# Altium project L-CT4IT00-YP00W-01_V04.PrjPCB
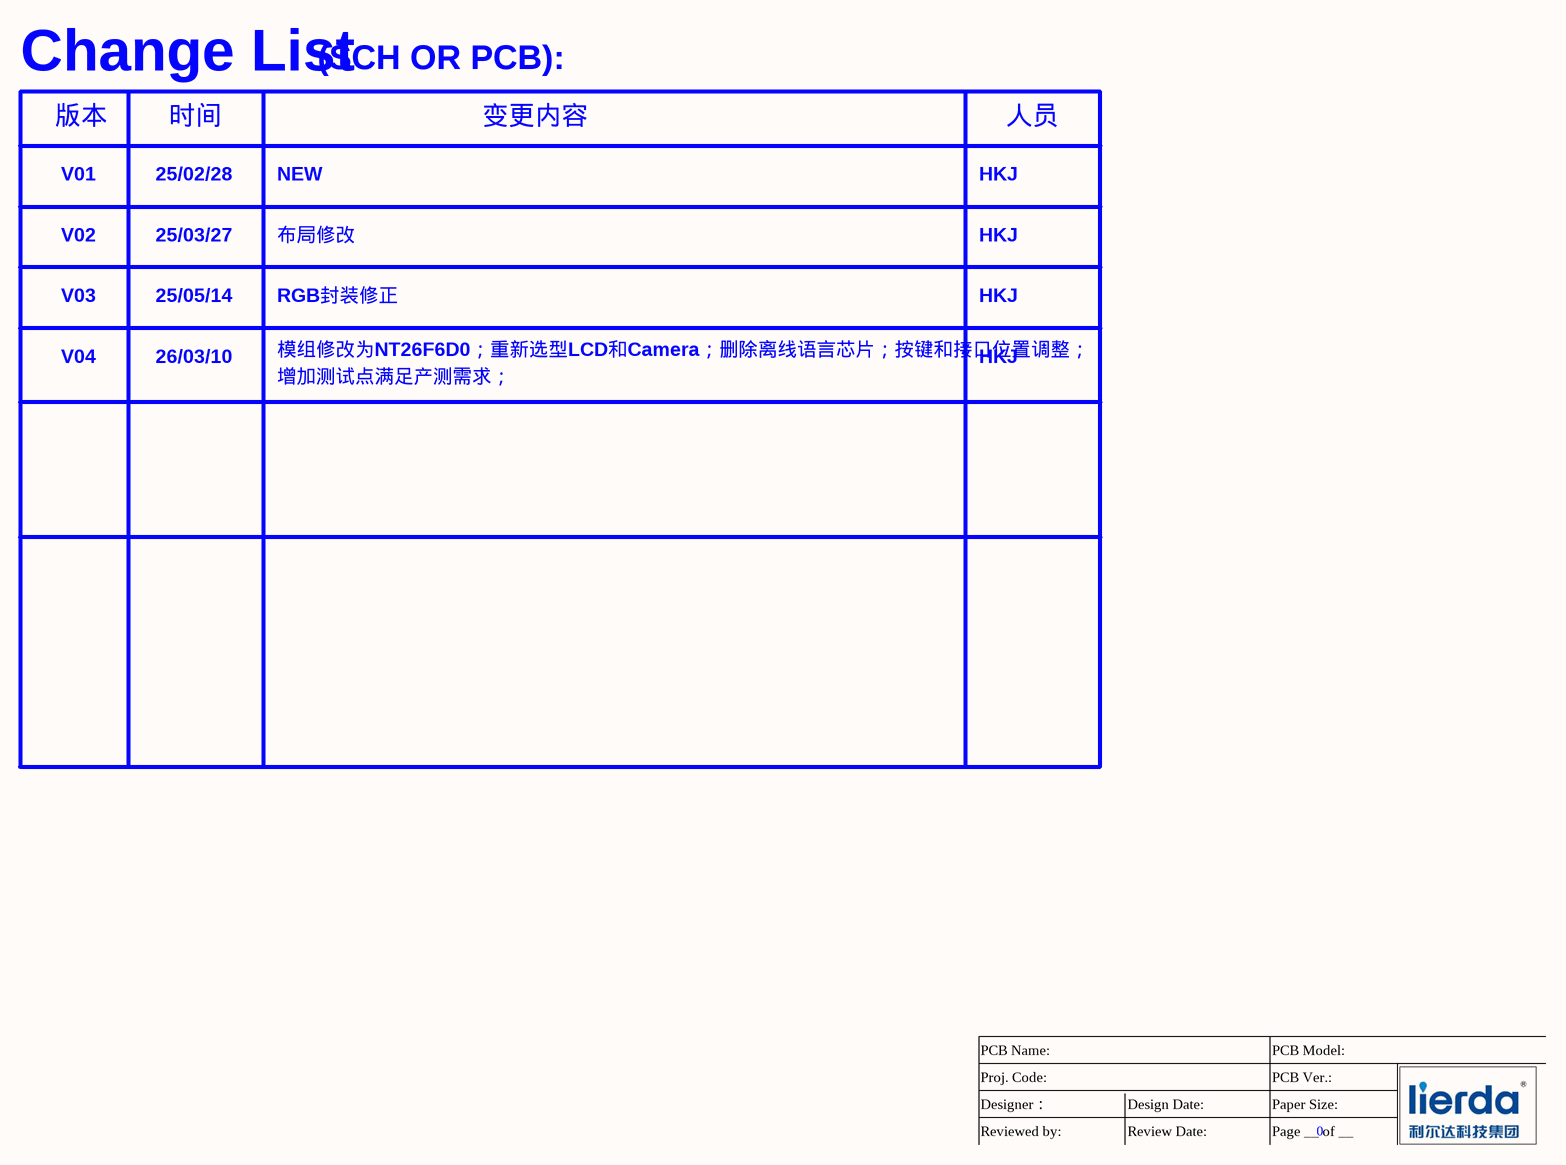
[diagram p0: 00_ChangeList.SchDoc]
项目型号: L-CT4IT00-YP00W-01; 项目名称: NT26FxDx OpenKit PCB; 立项编号: xxxx; 版本号: V04; 审核日期: 260318; 审核人员: SXT; 原理图页数: 4; 制图日期: 260317; 制图人员: HKJ
6 sheets, 214 parts. Net scope: global (net labels, ports and power ports of the same name join across sheets).
Board files: L-CT4IT00-YP00W-01_V04.PcbDoc, L-CT4IT00-YP00W-01-0402-04.PcbDoc
Sheets:
  00_ChangeList.SchDoc
  00_Block.SchDoc
  01_NT26FxDx.SchDoc
  02_Interfaces.SchDoc
  03_LED_KEY.SchDoc
  04_CODEC_PA.SchDoc

## Sheet 00_ChangeList.SchDoc
size A3

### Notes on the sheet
- Change List
- (SCH OR PCB):
- 版本
- V01
- 25/02/28
- 时间
- NEW
- 变更内容
- HKJ
- 人员
- V02
- 25/03/27
- 布局修改
- V03
- 25/05/14
- RGB封装修正
- V04
- 26/03/10
- 模组修改为NT26F6D0；重新选型LCD和Camera；删除离线语言芯片；按键和接口位置调整；
- 增加测试点满足产测需求；
- PCB Name:
- PCB Model:
- Designer：
- Proj. Code:
- Design Date:
- PCB Ver.:
- Paper Size:
- 0
- Reviewed by:
- Review Date:
- Page __ of __

## Sheet 00_Block.SchDoc
size A3
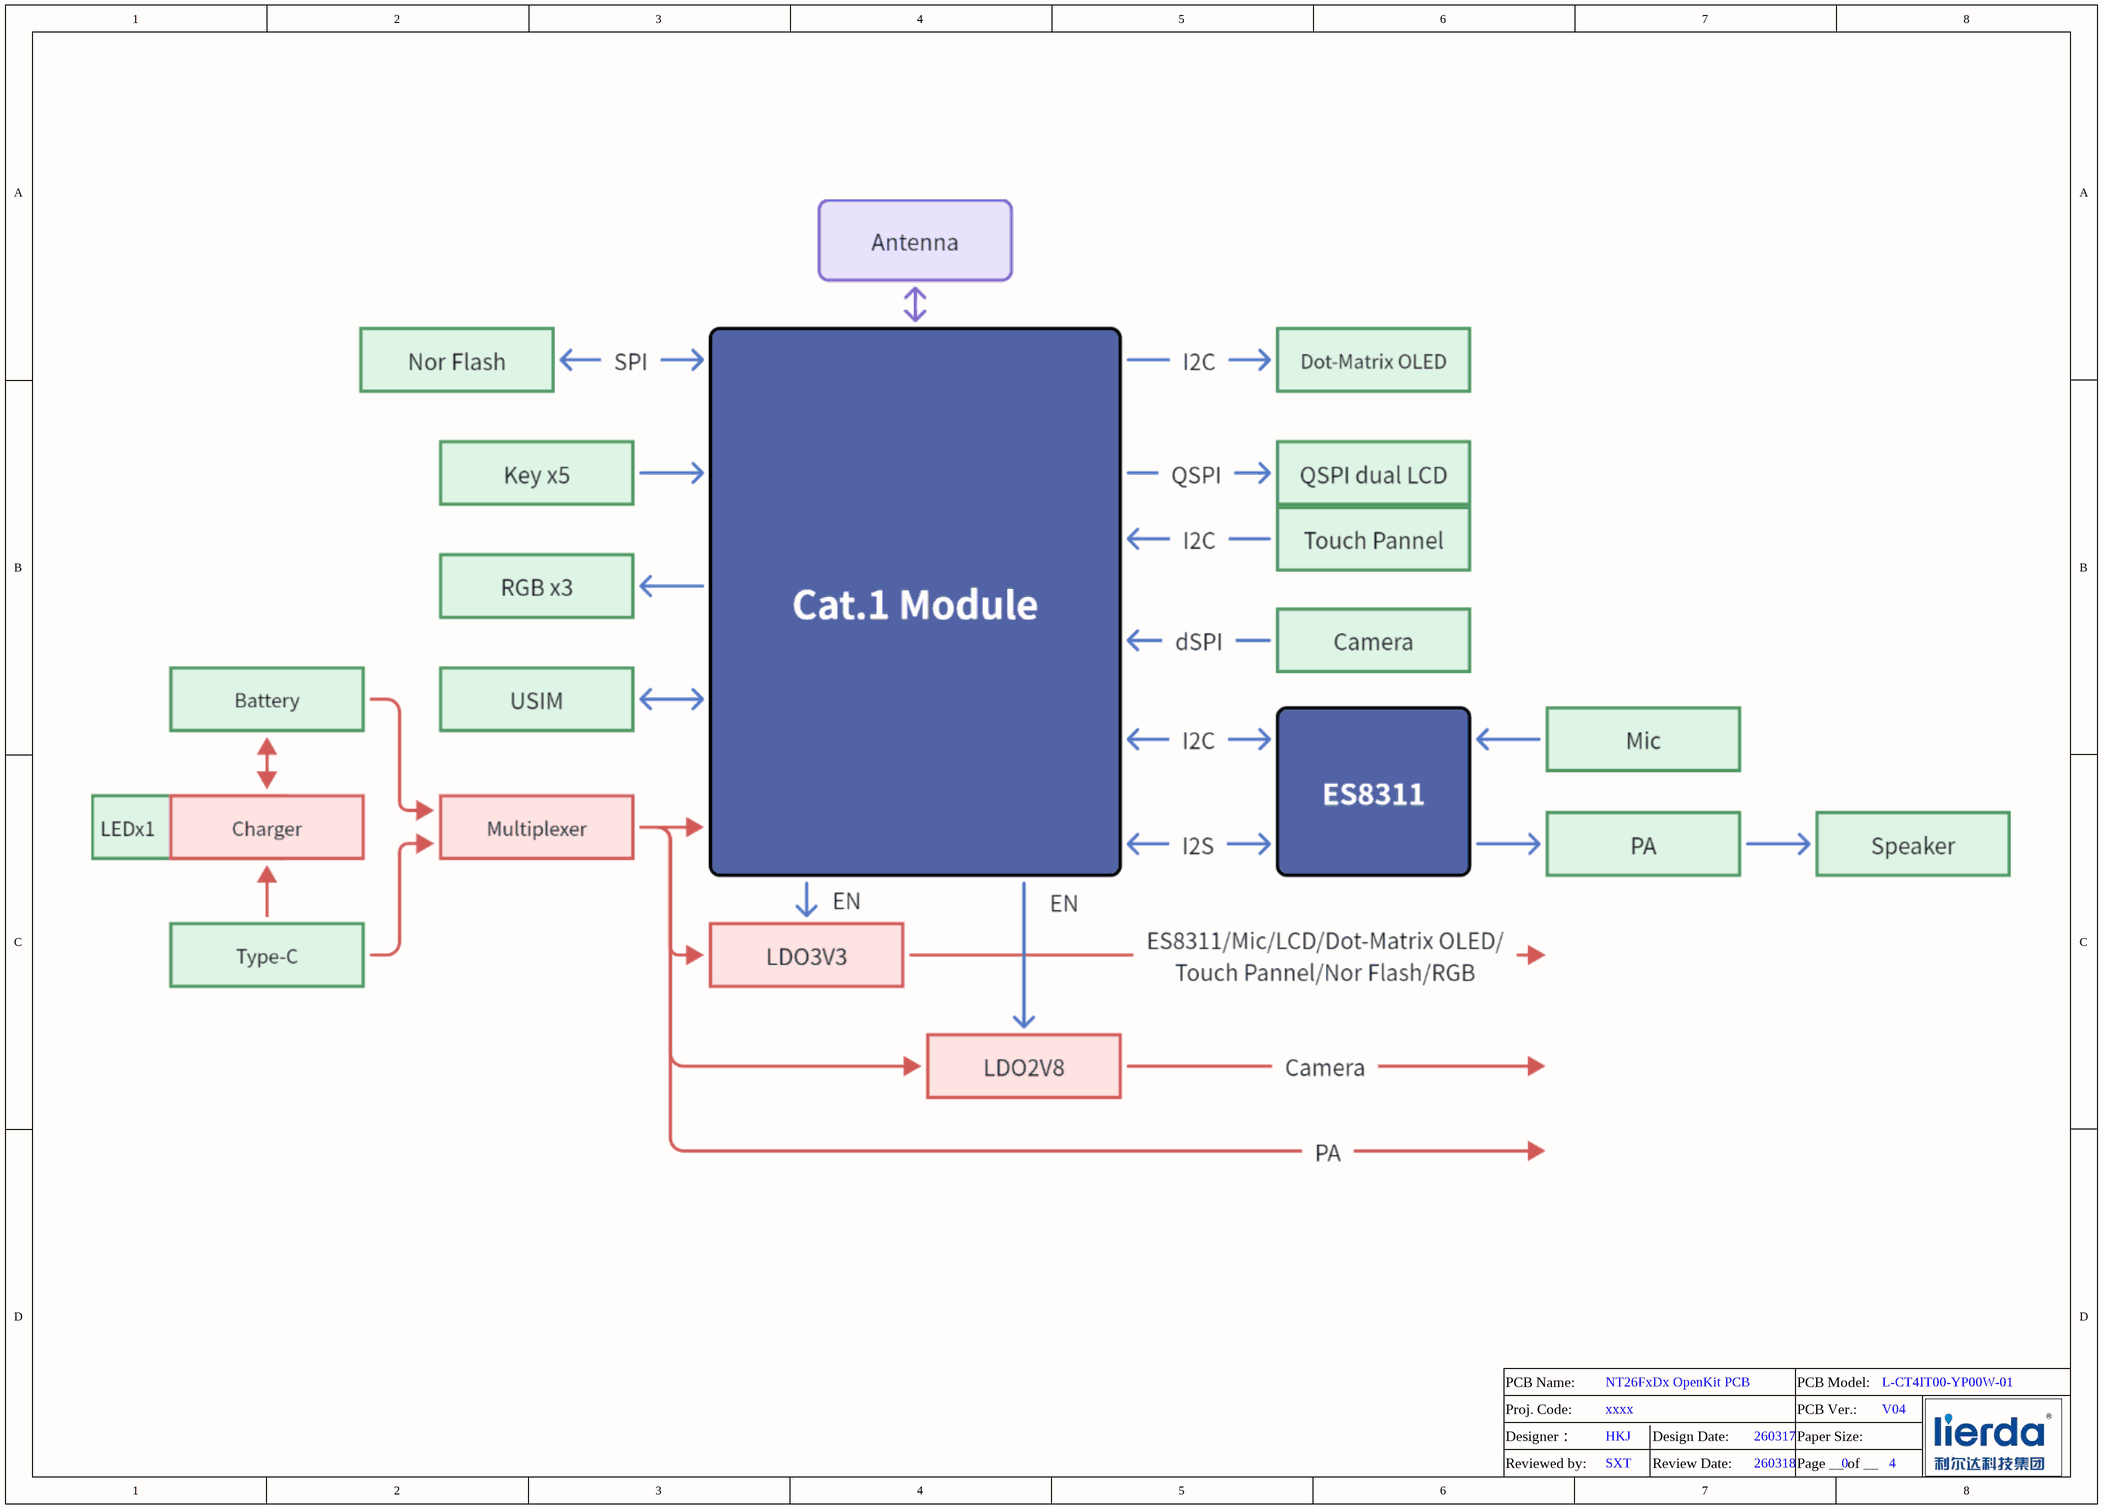
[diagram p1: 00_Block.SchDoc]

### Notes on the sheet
- PCB Name:
- PCB Model:
- Designer：
- Proj. Code:
- Design Date:
- PCB Ver.:
- Paper Size:
- 0
- Reviewed by:
- Review Date:
- Page __ of __

## Sheet 01_NT26FxDx.SchDoc
size A2
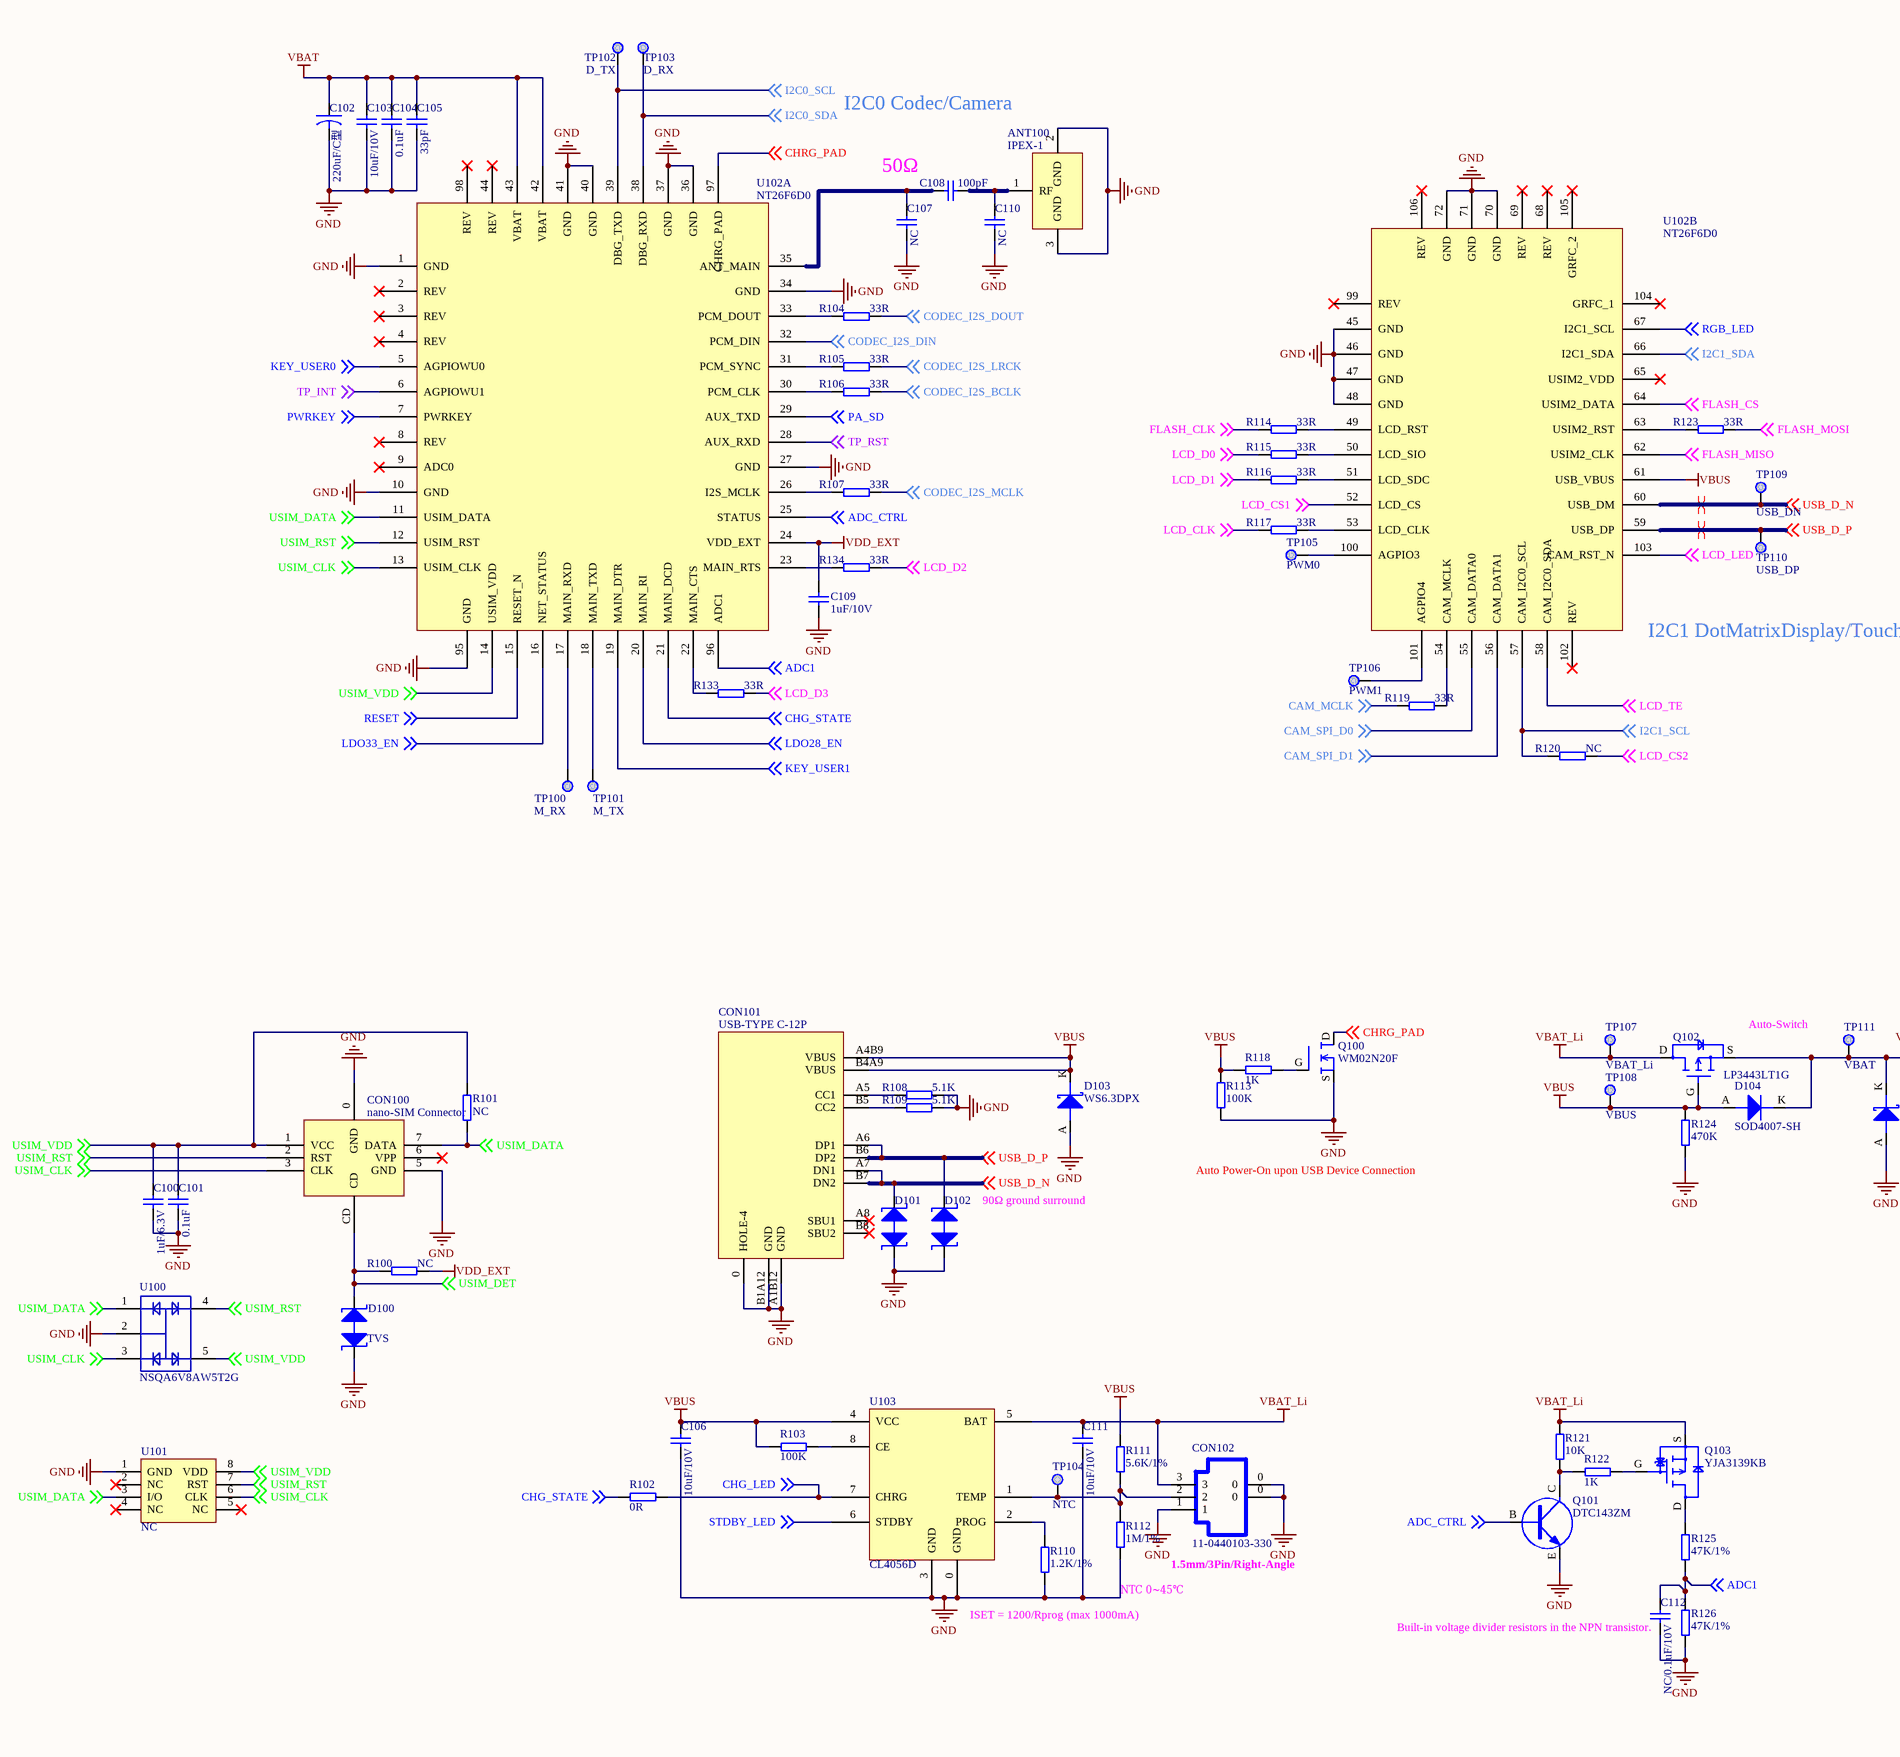
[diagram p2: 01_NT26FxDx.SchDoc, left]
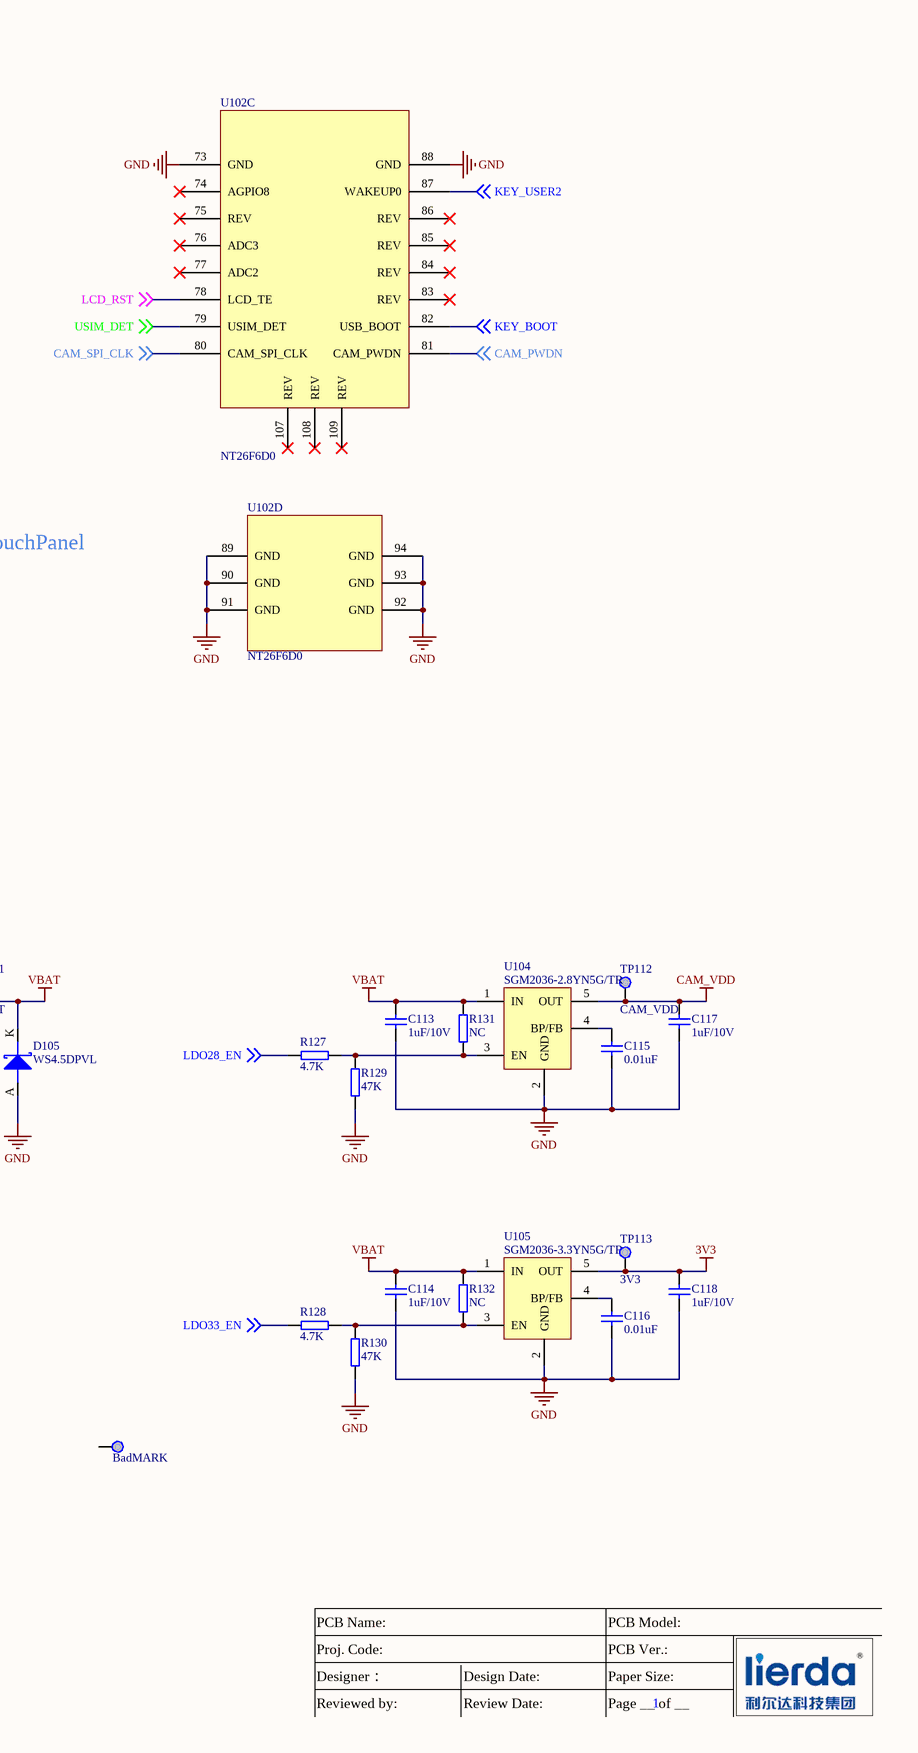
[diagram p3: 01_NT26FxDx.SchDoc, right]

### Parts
ANT100  IPEX-1  [IPX_U.FL-R-SMT-1]
BadMARK  BadMARK  [Bad Mark]  (value not drawn)
C100  1uF/6.3V  [0201_0.25D]
C101  0.1uF  [0201_0.25D]
C102  220uF/C型  [6032-TC]
C103  10uF/10V  [0402C_0.4D]
C104  0.1uF  [0201_0.25D]
C105  33pF  [0201_0.25D]
C106  10uF/10V  [0402C_0.4D]
C107  NC  [0201_0.25D]
C108  100pF  [0201_0.25D]
C109  1uF/10V  [0201_0.25D]
C110  NC  [0201_0.25D]
C111  10uF/10V  [0402C_0.4D]
C112  NC/0.1uF/10V  [0201_0.25D]
C113  1uF/10V  [0201_0.25D]
C114  1uF/10V  [0201_0.25D]
C115  0.01uF  [0201_0.25D]
C116  0.01uF  [0201_0.25D]
C117  1uF/10V  [0201_0.25D]
C118  1uF/10V  [0201_0.25D]
CON100  nano-SIM Connector  [SIM-MUP-C7801]
CON101  USB-TYPE C-12P  [TYPEC _6PIN板]
CON102  11-0440103-330  [SMD-1.5-3P]
D100  TVS  [DFN1006-NP]
D101  DIODE-2TVS-2  [DFN1006-NP]  (value not drawn)
D102  DIODE-2TVS-2  [DFN1006-NP]  (value not drawn)
D103  产品型号: WS6.3DPX  [UDFN2(1610)]  (hidden comment: DIODE-TVS)
D104  产品型号: SOD4007-SH  [SOD-123-FL]  (hidden comment: DIODE)
D105  产品型号: WS4.5DPVL  [UDFN2(1610)]  (hidden comment: DIODE-TVS)
Q100  WM02N20F  [DFN1006-3G]
Q101  DTC143ZM  [SOT-723-3A]
Q102  产品型号: LP3443LT1G  [SOT-23-3G]  (hidden comment: P-MOS-D1)
Q103  YJA3139KB  [DFN1006-3G]
R100  NC  [0201_0.25D]
R101  NC  [0201_0.25D]
R102  0R  [0201_0.25D]
R103  100K  [0201_0.25D]
R104  33R  [0201_0.25D]
R105  33R  [0201_0.25D]
R106  33R  [0201_0.25D]
R107  33R  [0201_0.25D]
R108  5.1K  [0201_0.25D]
R109  5.1K  [0201_0.25D]
R110  1.2K/1%  [0201_0.25D]
R111  5.6K/1%  [0201_0.25D]
R112  1M/1%  [0201_0.25D]
R113  100K  [0201_0.25D]
R114  33R  [0201_0.25D]
R115  33R  [0201_0.25D]
R116  33R  [0201_0.25D]
R117  33R  [0201_0.25D]
R118  1K  [0201_0.25D]
R119  33R  [0201_0.25D]
R120  NC  [0201_0.25D]
R121  10K  [0201_0.25D]
R122  1K  [0201_0.25D]
R123  33R  [0201_0.25D]
R124  470K  [0402R_0.4D]
R125  47K/1%  [0201_0.25D]
R126  47K/1%  [0201_0.25D]
R127  4.7K  [0201_0.25D]
R128  4.7K  [0201_0.25D]
R129  47K  [0201_0.25D]
R130  47K  [0201_0.25D]
R131  NC  [0201_0.25D]
R132  NC  [0201_0.25D]
R133  33R  [0201_0.25D]
R134  33R  [0201_0.25D]
TP100  M_RX  [TEST]
TP101  M_TX  [TEST]
TP102  D_TX  [TEST]
TP103  D_RX  [TEST]
TP104  NTC  [test]
TP105  PWM0  [TEST]
TP106  PWM1  [TEST]
TP107  VBAT_Li  [test]
TP108  VBUS  [test]
TP109  USB_DN  [test]
TP110  USB_DP  [test]
TP111  VBAT  [test]
TP112  CAM_VDD  [test]
TP113  3V3  [test]
U100  NSQA6V8AW5T2G  [SOT-323-5]
U101  NC  [DFN8(1.27)-6X5]
U102  NT26F6D0  [NT26-FCN B]  (parts A,B,C,D of 4)
U103  CL4056D  [SOP-8(1.27)-GND]
U104  产品型号: SGM2036-2.8YN5G/TR  [SOT-23-5P]  (hidden comment: SGM2036-XYN5G/TR)
U105  产品型号: SGM2036-3.3YN5G/TR  [SOT-23-5P]  (hidden comment: SGM2036-XYN5G/TR)

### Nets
3V3: C118.2 TP113.1 U105.5(OUT)
CAM_VDD: C117.2 TP112.1 U104.5(OUT)
GND: ANT100.2(GND) ANT100.3(GND) C100.1 C101.1 C102.2 C103.1 C104.1 C105.1 C106.1 C107.1 C109.1 C110.1 C111.1 C112.1 C113.1 C114.1 C115.1 C116.1 C117.1 C118.1 CON100.0(GND) CON100.5(GND) CON101.0(HOLE-4) CON101.A1B12(GND) CON101.B1A12(GND) CON102.0 CON102.1 D100.A D101.A D102.A D103.A D105.A Q100.S Q101.E R108.2 R109.2 R110.2 R112.2 R113.1 R124.1 R126.1 R129.1 R130.1 U100.2 U101.1(GND) U102.1(GND) U102.10(GND) U102.27(GND) U102.34(GND) U102.36(GND) U102.37(GND) U102.40(GND) U102.41(GND) U102.45(GND) U102.46(GND) U102.47(GND) U102.48(GND) U102.70(GND) U102.71(GND) U102.72(GND) U102.73(GND) U102.88(GND) U102.89(GND) U102.90(GND) U102.91(GND) U102.92(GND) U102.93(GND) U102.94(GND) U102.95(GND) U103.0(GND) U103.3(GND) U104.2(GND) U105.2(GND)
VBAT: C102.1 C103.2 C104.2 C105.2 C113.2 C114.2 D104.K D105.K Q102.S R131.1 R132.1 TP111.1 U102.42(VBAT) U102.43(VBAT) U104.1(IN) U105.1(IN)
VBAT_Li: C111.2 CON102.3 Q102.D Q103.S R121.2 TP107.1 U103.5(BAT)
VBUS: C106.2 CON101.A4B9(VBUS) CON101.B4A9(VBUS) D103.K D104.A Q102.G R103.2 R111.1 R113.2 R118.2 R124.2 TP108.1 U102.61(USB_VBUS) U103.4(VCC)
VDD_EXT: C109.2 R100.1 U102.24(VDD_EXT)
ADC1: C112.2 R125.1 R126.2 U102.96(ADC1) ; off-sheet ADC1
ADC_CTRL: Q101.B U102.25(STATUS) ; off-sheet ADC_CTRL
CAM_MCLK: R119.1 ; off-sheet CAM_MCLK
CAM_PWDN: U102.81(CAM_PWDN) ; off-sheet CAM_PWDN
CAM_SPI_CLK: U102.80(CAM_SPI_CLK) ; off-sheet CAM_SPI_CLK
CAM_SPI_D0: U102.55(CAM_DATA0) ; off-sheet CAM_SPI_D0
CAM_SPI_D1: U102.56(CAM_DATA1) ; off-sheet CAM_SPI_D1
CHG_LED: R102.2 U103.7(CHRG) ; off-sheet CHG_LED
CHG_STATE: R102.1 U102.21(MAIN_DCD) ; off-sheet CHG_STATE
CHRG_PAD: Q100.D U102.97(CHRG_PAD) ; off-sheet CHRG_PAD
CODEC_I2S_BCLK: R106.2 ; off-sheet CODEC_I2S_BCLK
CODEC_I2S_DIN: U102.32(PCM_DIN) ; off-sheet CODEC_I2S_DIN
CODEC_I2S_DOUT: R104.2 ; off-sheet CODEC_I2S_DOUT
CODEC_I2S_LRCK: R105.2 ; off-sheet CODEC_I2S_LRCK
CODEC_I2S_MCLK: R107.2 ; off-sheet CODEC_I2S_MCLK
FLASH_CLK: R114.2 ; off-sheet FLASH_CLK
FLASH_CS: U102.64(USIM2_DATA) ; off-sheet FLASH_CS
FLASH_MISO: U102.62(USIM2_CLK) ; off-sheet FLASH_MISO
FLASH_MOSI: R123.2 ; off-sheet FLASH_MOSI
I2C0_SCL: TP102.1 U102.39(DBG_TXD) ; off-sheet I2C0_SCL
I2C0_SDA: TP103.1 U102.38(DBG_RXD) ; off-sheet I2C0_SDA
I2C1_SCL: R120.1 U102.57(CAM_I2C0_SCL) ; off-sheet I2C1_SCL
I2C1_SDA: U102.66(I2C1_SDA) ; off-sheet I2C1_SDA
KEY_BOOT: U102.82(USB_BOOT) ; off-sheet KEY_BOOT
KEY_USER0: U102.5(AGPIOWU0) ; off-sheet KEY_USER0
KEY_USER1: U102.19(MAIN_DTR) ; off-sheet KEY_USER1
KEY_USER2: U102.87(WAKEUP0) ; off-sheet KEY_USER2
LCD_CLK: R117.1 ; off-sheet LCD_CLK
LCD_CS1: U102.52(LCD_CS) ; off-sheet LCD_CS1
LCD_CS2: R120.2 ; off-sheet LCD_CS2
LCD_D0: R115.1 ; off-sheet LCD_D0
LCD_D1: R116.1 ; off-sheet LCD_D1
LCD_D2: R134.2 ; off-sheet LCD_D2
LCD_D3: R133.2 ; off-sheet LCD_D3
LCD_LED: U102.103(CAM_RST_N) ; off-sheet LCD_LED
LCD_RST: U102.78(LCD_TE) ; off-sheet LCD_RST
LCD_TE: U102.58(CAM_I2C0_SDA) ; off-sheet LCD_TE
LDO28_EN: R127.1 U102.20(MAIN_RI) ; off-sheet LDO28_EN
LDO33_EN: R128.1 U102.16(NET_STATUS) ; off-sheet LDO33_EN
PA_SD: U102.29(AUX_TXD) ; off-sheet PA_SD
PWRKEY: U102.7(PWRKEY) ; off-sheet PWRKEY
RESET: U102.15(RESET_N) ; off-sheet RESET
RGB_LED: U102.67(I2C1_SCL) ; off-sheet RGB_LED
STDBY_LED: U103.6(STDBY) ; off-sheet STDBY_LED
TP_INT: U102.6(AGPIOWU1) ; off-sheet TP_INT
TP_RST: U102.28(AUX_RXD) ; off-sheet TP_RST
USB_D_N: CON101.A7(DN1) CON101.B7(DN2) D101.K TP109.1 U102.60(USB_DM) ; off-sheet USB_D_N
USB_D_P: CON101.A6(DP1) CON101.B6(DP2) D102.K TP110.1 U102.59(USB_DP) ; off-sheet USB_D_P
USIM_CLK: CON100.3(CLK) U100.3 U101.6(CLK) U102.13(USIM_CLK) ; off-sheet USIM_CLK
USIM_DATA: CON100.7(DATA) R101.1 U100.1 U101.3(I/O) U102.11(USIM_DATA) ; off-sheet USIM_DATA
USIM_DET: CON100.CD D100.K R100.2 U102.79(USIM_DET) ; off-sheet USIM_DET
USIM_RST: CON100.2(RST) U100.4 U101.7(RST) U102.12(USIM_RST) ; off-sheet USIM_RST
USIM_VDD: C100.2 C101.2 CON100.1(VCC) R101.2 U100.5 U101.8(VDD) U102.14(USIM_VDD) ; off-sheet USIM_VDD
NetANT100_1: ANT100.1(RF) C108.1 C110.2
NetC107_2: C107.2 C108.2 U102.35(ANT_MAIN)
NetC115_2: C115.2 U104.4(BP/FB)
NetC116_2: C116.2 U105.4(BP/FB)
NetCON101_A5: CON101.A5(CC1) R108.1
NetCON101_B5: CON101.B5(CC2) R109.1
NetCON102_2: CON102.2 R111.2 R112.1 TP104.1 U103.1(TEMP)
NetQ100_G: Q100.G R118.1
NetQ101_C: Q101.C R121.1 R122.2
NetQ103_D: Q103.D R125.2
NetQ103_G: Q103.G R122.1
NetR103_1: R103.1 U103.8(CE)
NetR104_1: R104.1 U102.33(PCM_DOUT)
NetR105_1: R105.1 U102.31(PCM_SYNC)
NetR106_1: R106.1 U102.30(PCM_CLK)
NetR107_1: R107.1 U102.26(I2S_MCLK)
NetR110_1: R110.1 U103.2(PROG)
NetR114_1: R114.1 U102.49(LCD_RST)
NetR115_2: R115.2 U102.50(LCD_SIO)
NetR116_2: R116.2 U102.51(LCD_SDC)
NetR117_2: R117.2 U102.53(LCD_CLK)
NetR119_2: R119.2 U102.54(CAM_MCLK)
NetR123_1: R123.1 U102.63(USIM2_RST)
NetR127_2: R127.2 R129.2 R131.2 U104.3(EN)
NetR128_2: R128.2 R130.2 R132.2 U105.3(EN)
NetR133_1: R133.1 U102.22(MAIN_CTS)
NetR134_1: R134.1 U102.23(MAIN_RTS)
NetTP100_1: TP100.1 U102.17(MAIN_RXD)
NetTP101_1: TP101.1 U102.18(MAIN_TXD)
NetTP105_1: TP105.1 U102.100(AGPIO3)
NetTP106_1: TP106.1 U102.101(AGPIO4)

Not connected (* = marked no-connect by the designer): BadMARK 1; CON100 6(VPP)*; CON101 A8(SBU1)* B8(SBU2)*; U101 2(NC)* 4(NC)* 5(NC)*; U102 2(REV)* 3(REV)* 4(REV)* 8(REV)* 9(ADC0)* 44(REV)* 65(USIM2_VDD)* 68(REV)* 69(REV)* 74(AGPIO8)* 75(REV)* 76(ADC3)* 77(ADC2)* 83(REV)* 84(REV)* 85(REV)* 86(REV)* 98(REV)* 99(REV)* 102(REV)* 104(GRFC_1)* 105(GRFC_2)* 106(REV)* 107(REV)* 108(REV)* 109(REV)*

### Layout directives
differential pair: USB_D_N, USB_D_P

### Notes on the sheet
- (near ANT100) I2C0 Codec/Camera
- 50Ω
- (near U102) I2C1 DotMatrixDisplay/TouchPanel
- Auto-Switch
- (near D102) 90Ω ground surround
- Auto Power‑On upon USB Device Connection
- (near R112) NTC 0~45℃
- 1.5mm/3Pin/Right-Angle
- ISET = 1200/Rprog (max 1000mA)
- Built-in voltage divider resistors in the NPN transistor.
- PCB Name:
- PCB Model:
- Designer：
- Reviewed by:
- Proj. Code:
- Design Date:
- Review Date:
- PCB Ver.:
- Paper Size:
- Page __ of __
- 1

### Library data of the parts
ANT100 = 1416000325: DC-6GHz; 产品型号: SL2-240006-A; 品名: RF测试座; 原厂品牌: 森岭; 封装: SMD; 物料状态: 优选
C100 C109 C112-C114 C117 C118 = 1405002136: 1uF/6.3V/20%/X5R; 产品型号: CL03A105MQ3CSNH; 品名: 陶瓷电容; 原厂品牌: SAMSUNG电容; 封装: 0201; 物料状态: 优选
C101 C104 = 1405001272: 0.1uF/10V/10%/X5R; 品名: 陶瓷电容; 原厂品牌: 微容VIIYONG; 封装: 0201; 物料状态: 优选
C102 = 1405000173: 220uF/6.3V/10%/1.2Ω; 产品型号: TAJC227K006RNJ; 品名: 钽电容; 原厂品牌: AVX; 封装: C型; 物料状态: 优选
C103 C106 C111 = 1405001308: 10uF/10V/20%/X5R; 产品型号: CL05A106MP5NUNC; 品名: 陶瓷电容; 原厂品牌: SAMSUNG电容; 封装: 0402; 物料状态: 优选
C105 C107 C108 C110 = 1405002411: 33pF/50V/5%/C0G; 产品型号: V330J0201C0G500NAT; 品名: 陶瓷电容; 原厂品牌: 微容VIIYONG; 封装: 0201; 物料状态: 优选
C115 C116 = 1405001481: 10nF/16V/10%/X7R; 产品型号: CC0201KRX7R7BB103; 品名: 陶瓷电容; 原厂品牌: YAGEO; 封装: 0201; 物料状态: 优选
CON100 = 1416003211: Push-Push NANO-SIM Card Connector; 产品型号: MUP-C7801-2; 品名: 卡座连接器; 原厂品牌: 德海威; 封装: SMD; 物料状态: 优选
CON101 = 1416003448: USB Type-C; 产品型号: U20405-2; 封装: SMD; 品名: USB连接器; 物料状态: 优选; 原厂品牌: 德海威
CON102 = 1416001211: 1.25mm/3PIN; 产品型号: CNT-W125-1*3-TDM-185; 存货编码: 1416002837; 品名: 线对板连接器; 原厂品牌: 肯耐特; 封装: SMD; 物料状态: 优选
D100 = 1409004149: 1通道; 产品型号: WS05DPF-BH; 品名: ESD保护器件; 原厂品牌: WAYON（维安）; 封装: DFN1006-2L; 物料状态: 优选
D101 D102 = 1409004148: 1通道; 产品型号: WS6183KF; 品名: ESD保护器件; 原厂品牌: WAYON（维安）; 封装: DFN1006-2L; 物料状态: 优选
D103 = 1409004319: 1通道; 品名: ESD保护器件; 原厂品牌: WAYON（维安）; 封装: DFN1610-2L; 物料状态: 优选
D104 = 1409001001: 1000V/1A; 品名: 整流二极管; 原厂品牌: LRC; 封装: SOD-123FL; 物料状态: 优选
D105 = 1409003028: 1通道/4.5V/12V/2160W/600pF; 品名: ESD保护器件; 原厂品牌: WAYON（维安）; 封装: DFN1610-2L; 物料状态: 优选
Q100 = N-MOS
Q101 = 1412002731: NPN/100mA/50V/100mW; 品名: 三极管; 原厂品牌: CJ; 封装: SOT-723; 物料状态: 优选
Q102 = 1412000290: PMOS/20V/4.7A; 品名: MOS管; 原厂品牌: LRC; 封装: SOT-23; 物料状态: 优选
Q103 = 1412003096: PMOS/-20V/0.65A; 品名: MOS管; 原厂品牌: YJ; 封装: DFN1006-3F; 物料状态: 优选
R100 R101 R103 R108 R109 R118 R121 R122 = 1408005605: 5.1KΩ/1%; 产品型号: 0201WMF5101TEE; 品名: 厚膜贴片电阻; 原厂品牌: Uniohm; 封装: 0201; 物料状态: 优选
R102 R110-R112 = 1408001444: 10KΩ/5%; 产品型号: RC0201JR-0710KL; 品名: 厚膜贴片电阻; 原厂品牌: YAGEO; 封装: 0201; 物料状态: 优选
R104-R107 R114-R117 R119 R120 R123 R133 R134 = 1408001443: 33Ω/5%; 产品型号: RC0201JR-0733RL; 品名: 厚膜贴片电阻; 原厂品牌: YAGEO; 封装: 0201; 物料状态: 优选
R113 = 1408005604: 10K/5%; 产品型号: 10K; 器件名称: 厚膜贴片电阻; 原厂品牌: Uniohm; 封装: 0201
R124 = 1408000869: 1M/5%; 产品型号: RC0402JR-071ML; 品名: 厚膜贴片电阻; 原厂品牌: YAGEO; 封装: 0402; 物料状态: 优选
R125 R126 R129 R130 = 1408001835: 47KΩ/1%; 产品型号: RC0201FR-0747KL; 品名: 厚膜贴片电阻; 原厂品牌: YAGEO; 封装: 0201; 物料状态: 优选
R127 R128 = 1408001558: 4.7KΩ/5%; 产品型号: RC0201JR-074K7L; 品名: 厚膜贴片电阻; 原厂品牌: YAGEO; 封装: 0201; 物料状态: 优选
R131 R132 = 1408005685: 100KΩ/5%; 产品型号: 0201WMJ0104TEE; 品名: 厚膜贴片电阻; 原厂品牌: Uniohm; 封装: 0201; 物料状态: 优选
TP100-TP103 TP105 TP106 = TP
TP104 TP107-TP113 = MARK
U100 = 1409000217: 双向/7.14V/600W; 器件名称: TVS管; 原厂品牌: Onsemi
U101 = 180006-03G: 存货编码: 1410013522; 封装: MFF2; 型号: 28991070003-FA; 品牌: 不指定（客供料）
U103 = CL4056
U104 = 1407001782: 2.8V/300mA/1.6-5.5V; 品名: 低压差线性稳压器; 原厂品牌: 圣邦微; 封装: SOT-23-5; 物料状态: 优选
U105 = 1407000926: 3.3V/300mA/1.6-5.5V; 品名: 低压差线性稳压器; 原厂品牌: 圣邦微; 封装: SOT-23-5; 物料状态: 优选

## Sheet 02_Interfaces.SchDoc
size A3
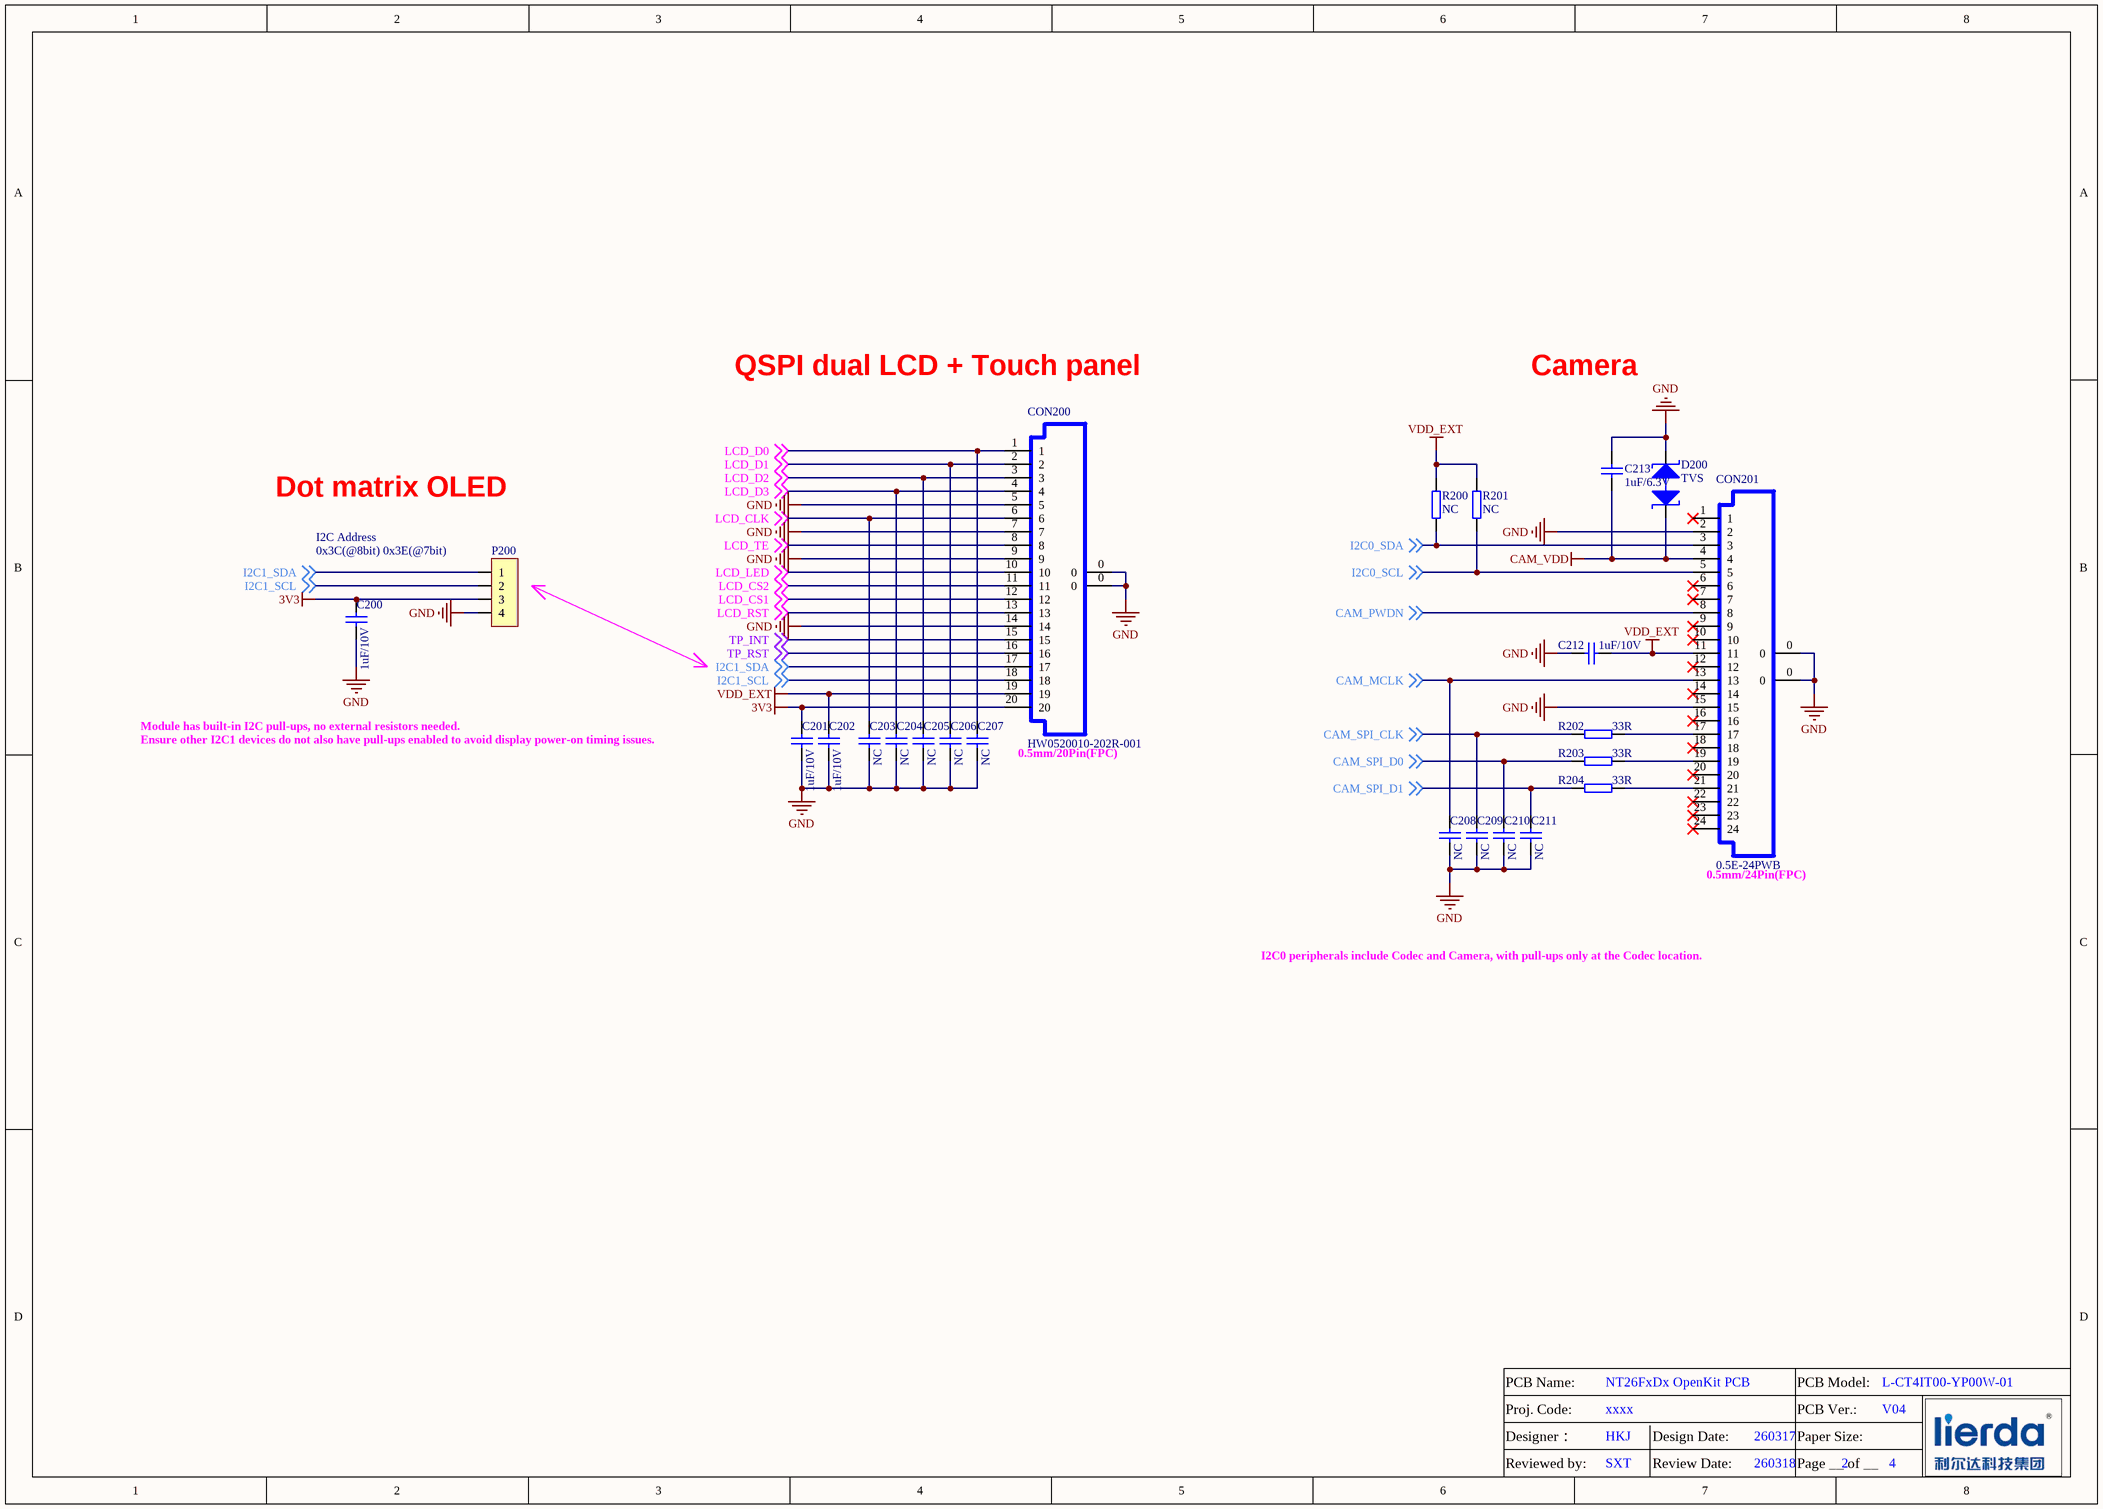
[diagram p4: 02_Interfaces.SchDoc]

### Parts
C200  1uF/10V  [0201_0.25D]
C201  1uF/10V  [0201_0.25D]
C202  1uF/10V  [0201_0.25D]
C203  NC  [0201_0.25D]
C204  NC  [0201_0.25D]
C205  NC  [0201_0.25D]
C206  NC  [0201_0.25D]
C207  NC  [0201_0.25D]
C208  NC  [0201_0.25D]
C209  NC  [0201_0.25D]
C210  NC  [0201_0.25D]
C211  NC  [0201_0.25D]
C212  1uF/10V  [0201_0.25D]
C213  1uF/6.3V  [0201_0.25D]
CON200  HW0520010-202R-001  [FPC0.5E-20P]
CON201  产品型号: 0.5E-24PWB  [0.5S-3S-24PWB]  (hidden comment: FPC-24)
D200  TVS  [DFN1006-NP]
P200  SPI 4-M  [SIP 2.54_4_S]  (value not drawn)
R200  NC  [0201_0.25D]
R201  NC  [0201_0.25D]
R202  33R  [0201_0.25D]
R203  33R  [0201_0.25D]
R204  33R  [0201_0.25D]

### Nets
3V3: C200.2 C201.1 CON200.20 P200.3
CAM_VDD: C213.1 CON201.4 D200.K
GND: C200.1 C201.2 C202.2 C203.1 C204.1 C205.1 C206.1 C207.1 C208.1 C209.1 C210.1 C211.1 C212.2 C213.2 CON200.0 CON200.5 CON200.7 CON200.9 CON200.14 CON201.0 CON201.2 CON201.15 D200.A P200.4
VDD_EXT: C202.1 C212.1 CON200.19 CON201.11 R200.2 R201.2
CAM_MCLK: C208.2 CON201.13 ; off-sheet CAM_MCLK
CAM_PWDN: CON201.8 ; off-sheet CAM_PWDN
CAM_SPI_CLK: C209.2 R202.1 ; off-sheet CAM_SPI_CLK
CAM_SPI_D0: C210.2 R203.1 ; off-sheet CAM_SPI_D0
CAM_SPI_D1: C211.2 R204.1 ; off-sheet CAM_SPI_D1
I2C0_SCL: CON201.5 R201.1 ; off-sheet I2C0_SCL
I2C0_SDA: CON201.3 R200.1 ; off-sheet I2C0_SDA
I2C1_SCL: CON200.18 P200.2 ; off-sheet I2C1_SCL
I2C1_SDA: CON200.17 P200.1 ; off-sheet I2C1_SDA
LCD_CLK: C203.2 CON200.6 ; off-sheet LCD_CLK
LCD_CS1: CON200.12 ; off-sheet LCD_CS1
LCD_CS2: CON200.11 ; off-sheet LCD_CS2
LCD_D0: C207.2 CON200.1 ; off-sheet LCD_D0
LCD_D1: C206.2 CON200.2 ; off-sheet LCD_D1
LCD_D2: C205.2 CON200.3 ; off-sheet LCD_D2
LCD_D3: C204.2 CON200.4 ; off-sheet LCD_D3
LCD_LED: CON200.10 ; off-sheet LCD_LED
LCD_RST: CON200.13 ; off-sheet LCD_RST
LCD_TE: CON200.8 ; off-sheet LCD_TE
TP_INT: CON200.15 ; off-sheet TP_INT
TP_RST: CON200.16 ; off-sheet TP_RST
NetCON201_17: CON201.17 R202.2
NetCON201_19: CON201.19 R203.2
NetCON201_21: CON201.21 R204.2

Not connected (* = marked no-connect by the designer): CON201 1* 6* 7* 9* 10* 12* 14* 16* 18* 20* 22* 23* 24*

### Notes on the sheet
- QSPI dual LCD + Touch panel
- Camera
- Dot matrix OLED
- I2C Address
- 0x3C(@8bit) 0x3E(@7bit)
- Module has built-in I2C pull-ups, no external resistors needed.
- Ensure other I2C1 devices do not also have pull-ups enabled to avoid display power-on timing issues.
- 0.5mm/20Pin(FPC)
- (near CON201) 0.5mm/24Pin(FPC)
- I2C0 peripherals include Codec and Camera, with pull-ups only at the Codec location.
- PCB Name:
- PCB Model:
- Designer：
- Proj. Code:
- Design Date:
- PCB Ver.:
- Paper Size:
- 2
- Reviewed by:
- Review Date:
- Page __ of __

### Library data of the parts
C200-C202 C212 C213 = 1405002136: as C100 on sheet 01_NT26FxDx
C203-C211 = 1405002411: as C105 on sheet 01_NT26FxDx
CON200 = 1416002856: 0.50mm/20PIN; 产品型号: 60030-2001-5002; 品名: FFC，FPC连接器; 原厂品牌: 新富尔; 封装: SMD; 物料状态: 优选
CON201 = 1416000423: 0.50mm/24PIN; 品名: FFC，FPC连接器; 原厂品牌: 乐清华宝; 封装: SMD; 物料状态: 优选
D200 = 1409004149: as D100 on sheet 01_NT26FxDx
P200 = 1416000794: 2.54mm/1*4PIN/直; 产品型号: PH2.54排针1X4P/L=11.6 PA=6 PC=3 H=2.5; 品名: 排针; 原厂品牌: 联益; 封装: DIP; 物料状态: 优选
R200 R201 = 1408005605: as R100 on sheet 01_NT26FxDx
R202-R204 = 1408001443: as R104 on sheet 01_NT26FxDx

## Sheet 03_LED_KEY.SchDoc
size A3
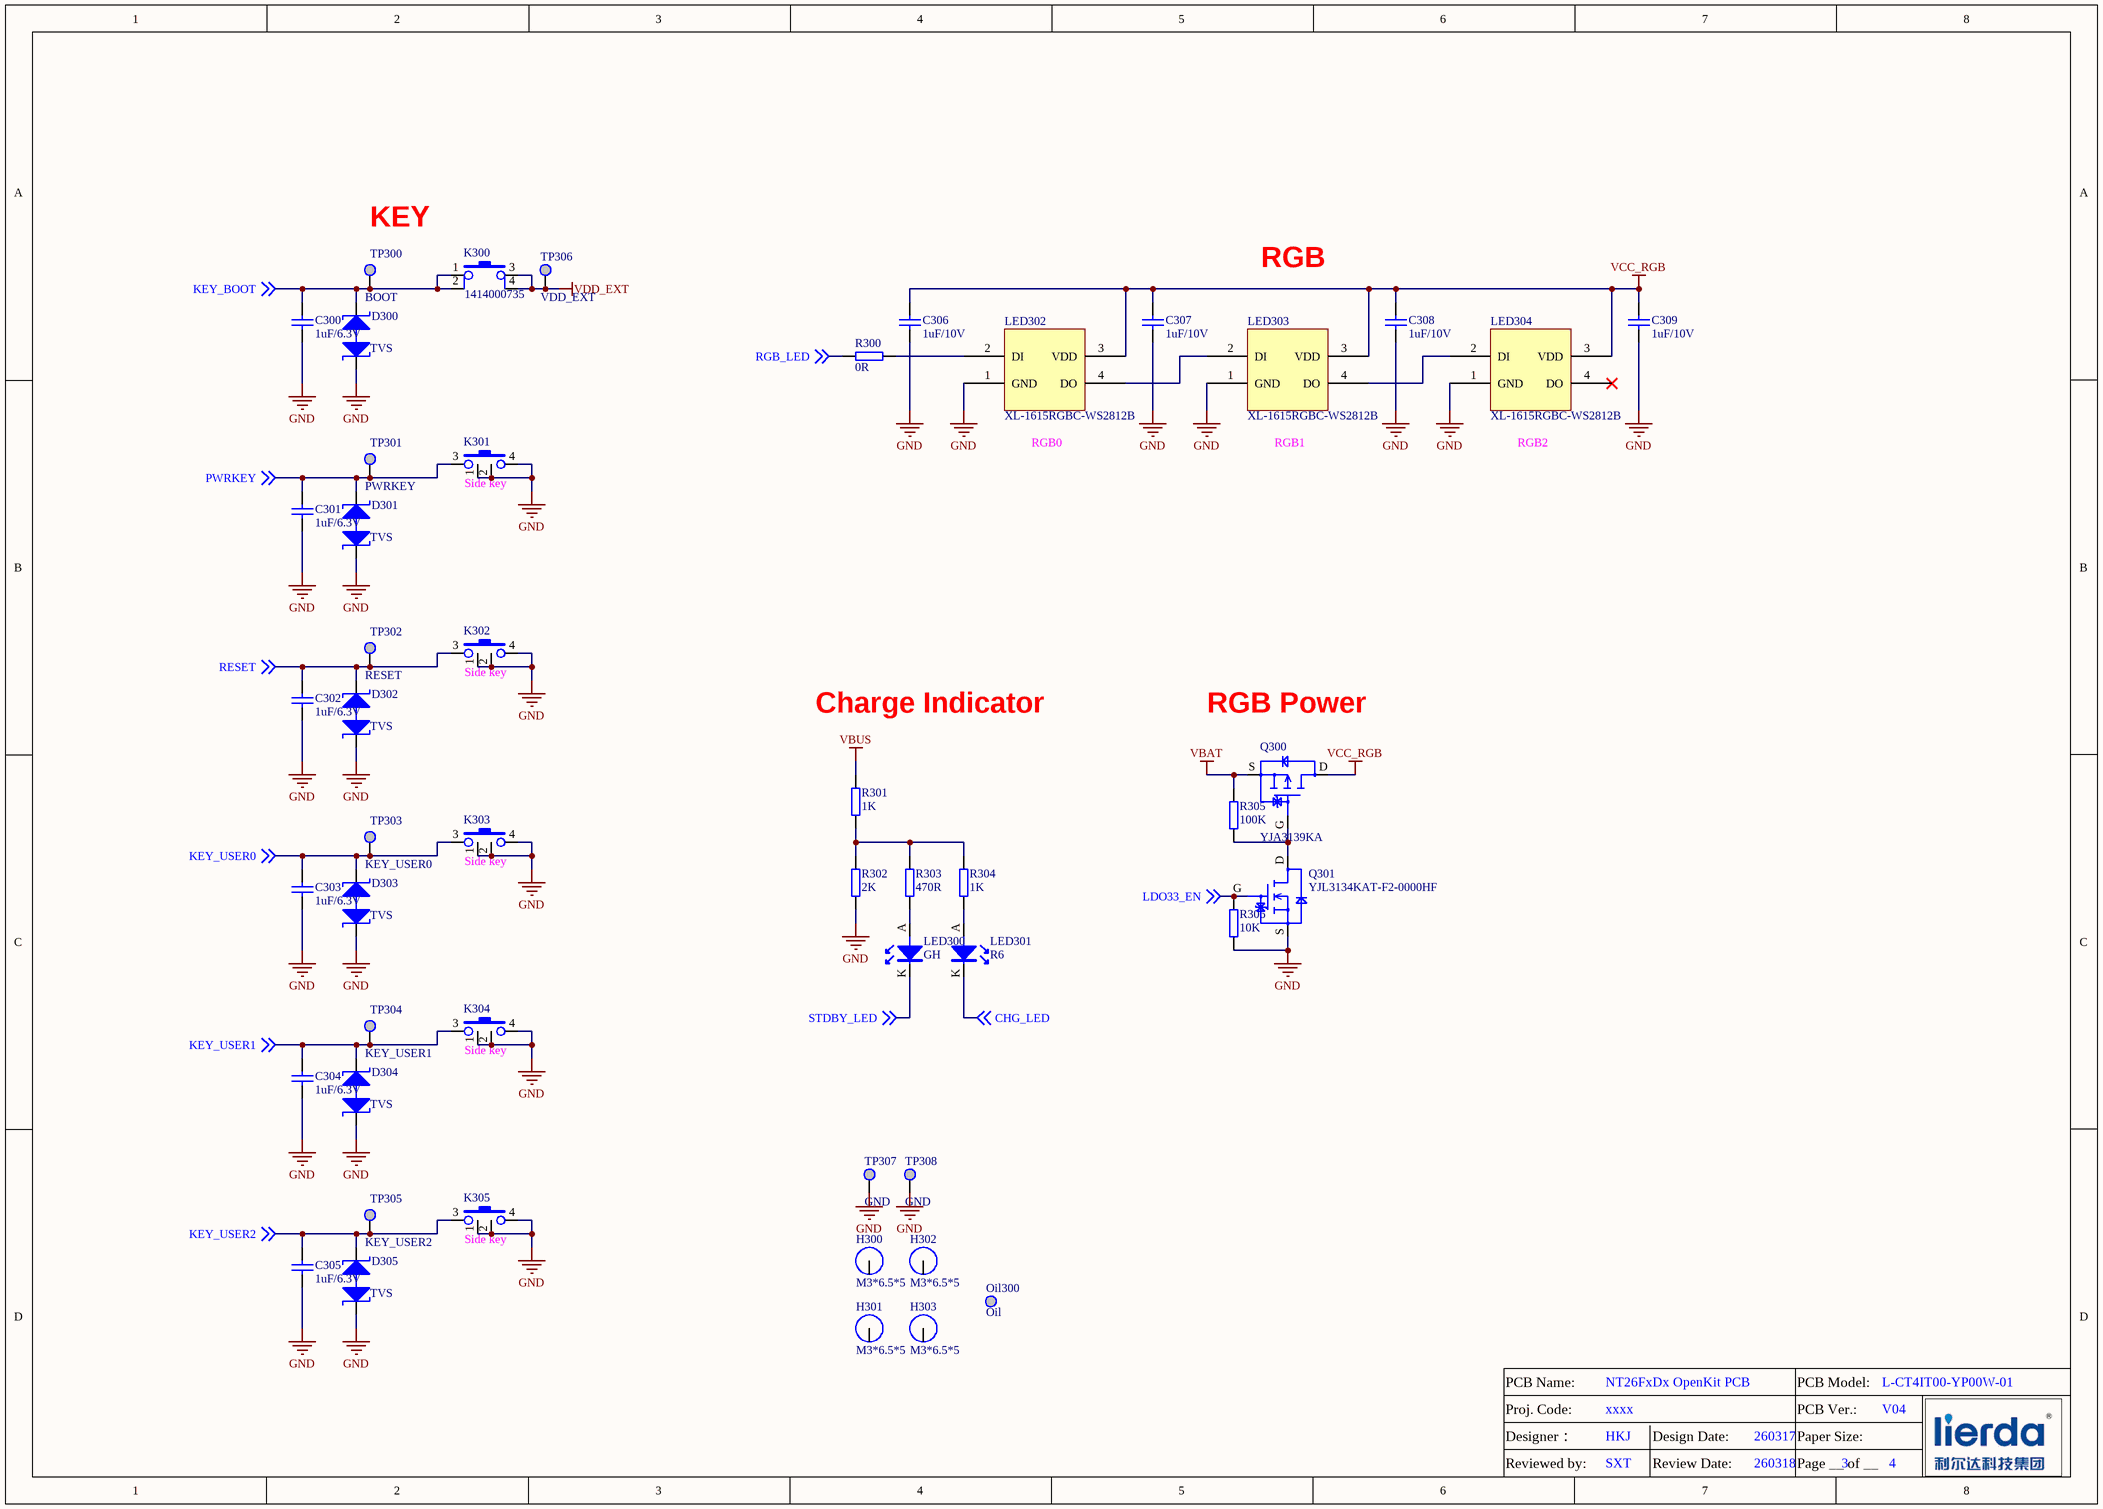
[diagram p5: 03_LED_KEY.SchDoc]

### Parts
C300  1uF/6.3V  [0201_0.25D]
C301  1uF/6.3V  [0201_0.25D]
C302  1uF/6.3V  [0201_0.25D]
C303  1uF/6.3V  [0201_0.25D]
C304  1uF/6.3V  [0201_0.25D]
C305  1uF/6.3V  [0201_0.25D]
C306  1uF/10V  [0201_0.25D]
C307  1uF/10V  [0201_0.25D]
C308  1uF/10V  [0201_0.25D]
C309  1uF/10V  [0201_0.25D]
D300  TVS  [DFN1006-NP]
D301  TVS  [DFN1006-NP]
D302  TVS  [DFN1006-NP]
D303  TVS  [DFN1006-NP]
D304  TVS  [DFN1006-NP]
D305  TVS  [DFN1006-NP]
H300  M3*6.5*5  [Toolinghole]
H301  M3*6.5*5  [Toolinghole]
H302  M3*6.5*5  [Toolinghole]
H303  M3*6.5*5  [Toolinghole]
K300  1414000735  [TS3443-0253B]
K301  BUTTON-2-2  [SW-7.8X3.5-4P-HOLE-S]  (value not drawn)
K302  BUTTON-2-2  [SW-7.8X3.5-4P-HOLE-S]  (value not drawn)
K303  BUTTON-2-2  [SW-7.8X3.5-4P-HOLE-S]  (value not drawn)
K304  BUTTON-2-2  [SW-7.8X3.5-4P-HOLE-S]  (value not drawn)
K305  BUTTON-2-2  [SW-7.8X3.5-4P-HOLE-S]  (value not drawn)
LED300  GH  [D0402]
LED301  R6  [D0402]
LED302  XL-1615RGBC-WS2812B  [D1615RGBC]
LED303  XL-1615RGBC-WS2812B  [D1615RGBC]
LED304  XL-1615RGBC-WS2812B  [D1615RGBC]
Oil300  Oil  [White oil-6X6]
Q300  产品型号: YJA3139KA  [DFN1006-3G]  (hidden comment: P-MOS-D)
Q301  产品型号: YJL3134KAT-F2-0000HF  [SOT-723-3G]  (hidden comment: N-MOS-D)
R300  0R  [0201_0.25D]
R301  1K  [0201C_0.2D(NB)]
R302  2K  [0201C_0.2D(NB)]
R303  470R  [0201C_0.2D(NB)]
R304  1K  [0201C_0.2D(NB)]
R305  100K  [0201_0.25D]
R306  10K  [0201_0.25D]
TP300  BOOT  [test]
TP301  PWRKEY  [test]
TP302  RESET  [test]
TP303  KEY_USER0  [test]
TP304  KEY_USER1  [test]
TP305  KEY_USER2  [test]
TP306  VDD_EXT  [test]
TP307  GND  [test]
TP308  GND  [test]

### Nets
GND: C300.1 C301.1 C302.1 C303.1 C304.1 C305.1 C306.2 C307.2 C308.2 C309.2 D300.A D301.A D302.A D303.A D304.A D305.A K301.1 K301.2 K301.4 K302.1 K302.2 K302.4 K303.1 K303.2 K303.4 K304.1 K304.2 K304.4 K305.1 K305.2 K305.4 LED302.1(GND) LED303.1(GND) LED304.1(GND) Q301.S R302.1 R306.1 TP307.1 TP308.1
VBAT: Q300.S R305.1
VBUS: R301.2
VCC_RGB: C306.1 C307.1 C308.1 C309.1 LED302.3(VDD) LED303.3(VDD) LED304.3(VDD) Q300.D
VDD_EXT: K300.3 K300.4 TP306.1
CHG_LED: LED301.K ; off-sheet CHG_LED
KEY_BOOT: C300.2 D300.K K300.1 K300.2 TP300.1 ; off-sheet KEY_BOOT
KEY_USER0: C303.2 D303.K K303.3 TP303.1 ; off-sheet KEY_USER0
KEY_USER1: C304.2 D304.K K304.3 TP304.1 ; off-sheet KEY_USER1
KEY_USER2: C305.2 D305.K K305.3 TP305.1 ; off-sheet KEY_USER2
LDO33_EN: Q301.G R306.2 ; off-sheet LDO33_EN
PWRKEY: C301.2 D301.K K301.3 TP301.1 ; off-sheet PWRKEY
RESET: C302.2 D302.K K302.3 TP302.1 ; off-sheet RESET
RGB_LED: R300.2 ; off-sheet RGB_LED
STDBY_LED: LED300.K ; off-sheet STDBY_LED
NetLED300_A: LED300.A R303.1
NetLED301_A: LED301.A R304.1
NetLED302_2: LED302.2(DI) R300.1
NetLED302_4: LED302.4(DO) LED303.2(DI)
NetLED303_4: LED303.4(DO) LED304.2(DI)
NetQ300_G: Q300.G Q301.D R305.2
NetR301_1: R301.1 R302.2 R303.2 R304.2

Not connected (* = marked no-connect by the designer): H300 1(H); H301 1(H); H302 1(H); H303 1(H); LED304 4(DO)*

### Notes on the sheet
- (near TP300) KEY
- RGB
- RGB0
- RGB1
- RGB2
- (near K301) Side key
- (near K302) Side key
- Charge Indicator
- RGB Power
- (near K303) Side key
- (near K304) Side key
- (near K305) Side key
- PCB Name:
- PCB Model:
- Designer：
- Proj. Code:
- Design Date:
- PCB Ver.:
- Paper Size:
- 3
- Reviewed by:
- Review Date:
- Page __ of __

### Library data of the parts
C300-C309 = 1405002136: as C100 on sheet 01_NT26FxDx
D300-D305 = 1409004149: as D100 on sheet 01_NT26FxDx
H300-H303 = 1602002834: M3*6.5*5/铜; 产品型号: M3x6.5x5铜螺柱 卷带包装; 品名: 螺柱; 原厂品牌: 磊森晶通信; 封装: SMD; 物料状态: 限用
K300 = 1416003591: 6*6*7.3; 产品型号: JY-TS6060-H7.3-AA26F; 品名: 轻触开关; 原厂品牌: 温达; 封装: SMD; 物料状态: 优选
K301-K305 = 1414000145: 7.8*3.5*3.5; 产品型号: 1188E-1K2-V-T/R; 品名: 轻触开关; 原厂品牌: DIPTRONICS; 封装: SMD; 物料状态: 限用
LED300 = 1409003070: 绿/25mA/112-225mcd; 产品型号: 16-213/GHC-YR1S1N/3T; 品名: LED发光二极管; 原厂品牌: EVERLIGHT; 封装: 0402; 物料状态: 优选
LED301 = 1409000384: 红/25mA/40mcd; 产品型号: 16-213SURC/S530-A3/TR8; 品名: LED发光二极管; 原厂品牌: EVERLIGHT; 封装: 0402; 物料状态: 优选
LED302-LED304 = WS2812B: 料号: 1409003483
Q300 = 1412003017: PMOS/20V/0.65A; 品名: MOS管; 原厂品牌: YJ; 封装: DFN1006-3L; 物料状态: 优选
Q301 = 1412003327: NMOS/20V/0.5A; 品名: MOS管; 原厂品牌: YJ; 封装: SOT-723; 物料状态: 优选
R300-R304 = 1408005605: as R100 on sheet 01_NT26FxDx
R305 = 1408005685: as R131 on sheet 01_NT26FxDx
R306 = 1408001444: as R102 on sheet 01_NT26FxDx
TP300-TP308 = MARK

## Sheet 04_CODEC_PA.SchDoc
size A3; SheetNumber: 3; SheetTotal: 7
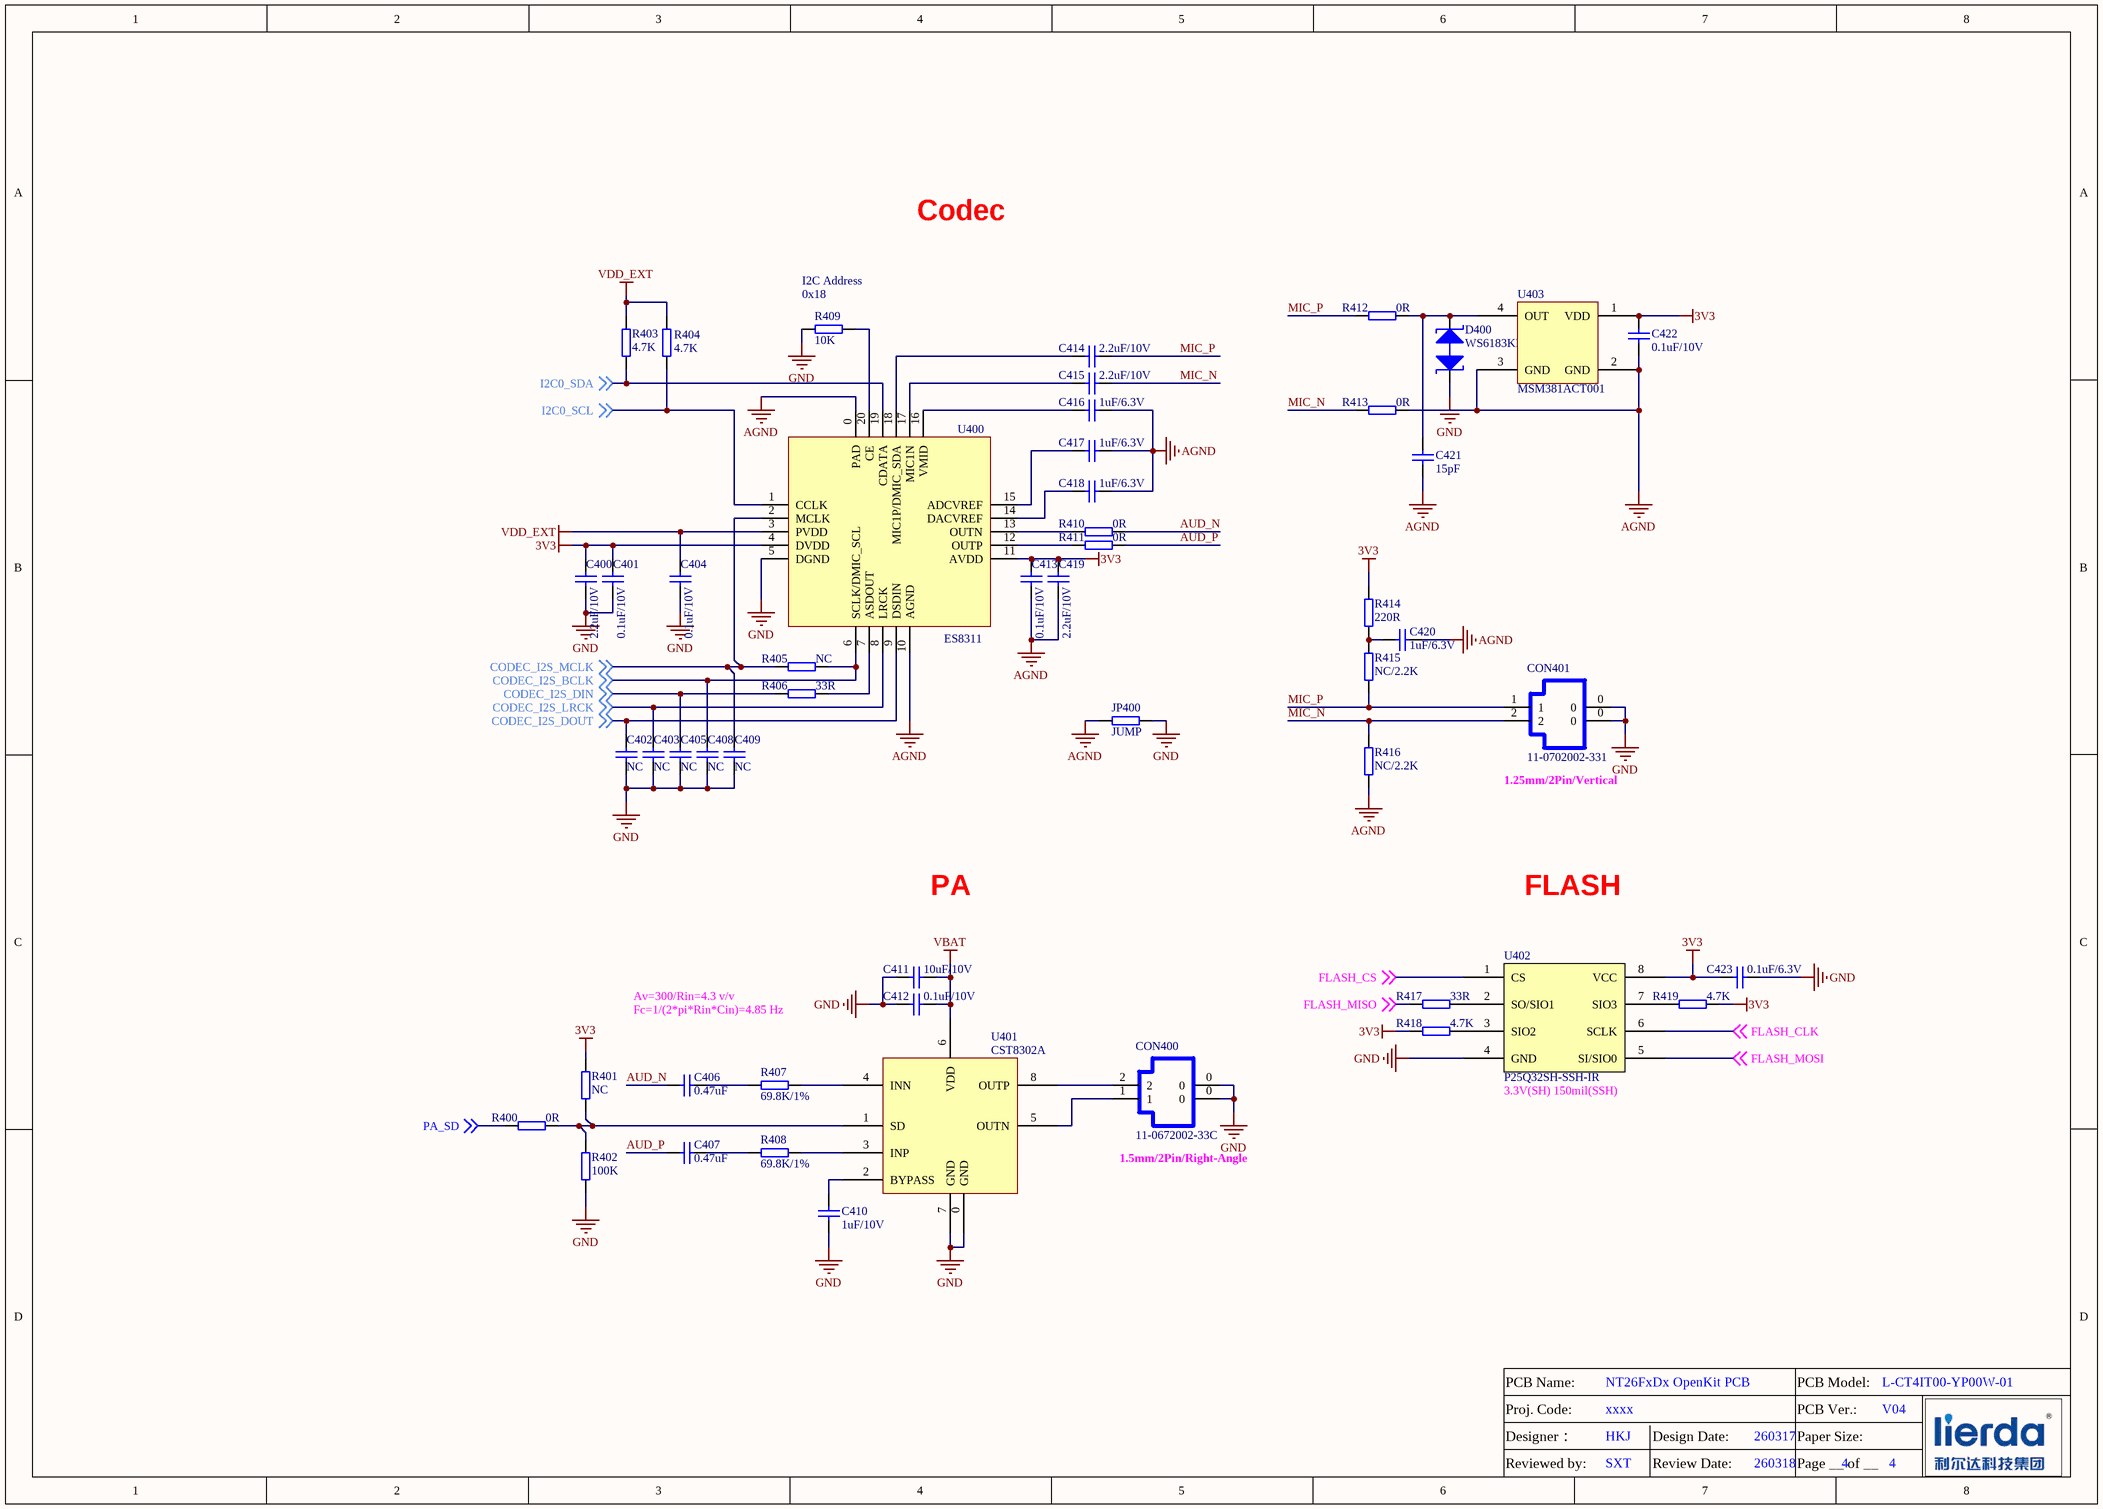
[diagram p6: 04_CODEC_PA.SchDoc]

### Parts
C400  2.2uF/10V  [0402C_0.4D-NB]
C401  0.1uF/10V  [0201_0.25D]
C402  NC  [0201_0.25D]
C403  NC  [0201_0.25D]
C404  0.1uF/10V  [0201_0.25D]
C405  NC  [0201_0.25D]
C406  0.47uF  [0201_0.25D]
C407  0.47uF  [0201_0.25D]
C408  NC  [0201_0.25D]
C409  NC  [0201_0.25D]
C410  1uF/10V  [0201_0.25D]
C411  10uF/10V  [0402C_0.4D]
C412  0.1uF/10V  [0201_0.25D]
C413  0.1uF/10V  [0201_0.25D]
C414  2.2uF/10V  [0402C_0.4D-NB]
C415  2.2uF/10V  [0402C_0.4D-NB]
C416  1uF/6.3V  [0201_0.25D]
C417  1uF/6.3V  [0201_0.25D]
C418  1uF/6.3V  [0201_0.25D]
C419  2.2uF/10V  [0402C_0.4D-NB]
C420  1uF/6.3V  [0201_0.25D]
C421  15pF  [0201C_0.2D(NB)]
C422  0.1uF/10V  [0201C_0.2D(NB)]
C423  0.1uF/6.3V  [0201_0.25D]
CON400  11-0672002-33C  [SMD-1.5-2P]
CON401  11-0702002-331  [SMD-1.25-2P]
D400  WS6183KF  [DFN1006-NP]
JP400  JUMP  [0402R_0.4D_JP]
R400  0R  [0201_0.25D]
R401  NC  [0201_0.25D]
R402  100K  [0201_0.25D]
R403  4.7K  [0201_0.25D]
R404  4.7K  [0201_0.25D]
R405  NC  [0201_0.25D]
R406  33R  [0201_0.25D]
R407  69.8K/1%  [0201_0.25D]
R408  69.8K/1%  [0201_0.25D]
R409  10K  [0201_0.25D]
R410  0R  [0201_0.25D]
R411  0R  [0201_0.25D]
R412  0R  [0201C_0.2D(NB)]
R413  0R  [0201C_0.2D(NB)]
R414  220R  [0201_0.25D]
R415  NC/2.2K  [0201_0.25D]
R416  NC/2.2K  [0201_0.25D]
R417  33R  [0201_0.25D]
R418  4.7K  [0201_0.25D]
R419  4.7K  [0201_0.25D]
U400  ES8311  [QFN20(0.4)-3X3]
U401  CST8302A  [SOP-8(1.27)-GND]
U402  P25Q32SH-SSH-IR  [SOP-8(1.27)]
U403  MSM381ACT001  [麦克风MSM381ACT001]

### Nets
3V3: C400.2 C401.1 C413.1 C419.2 C422.2 C423.2 R401.2 R414.2 R418.1 R419.2 U400.4(DVDD) U400.11(AVDD) U402.8(VCC) U403.1(VDD)
AGND: C413.2 C416.1 C417.1 C418.1 C419.1 C420.2 C421.1 C422.1 JP400.1 R413.1 R416.1 U400.0(PAD) U400.10(AGND) U403.2(GND) U403.3(GND)
GND: C400.1 C401.2 C402.1 C403.1 C404.2 C405.1 C408.1 C409.1 C410.1 C411.2 C412.1 C423.1 CON400.0 CON401.0 D400.A JP400.2 R402.1 R409.2 U400.5(DGND) U401.0(GND) U401.7(GND) U402.4(GND)
VBAT: C411.1 C412.2 U401.6(VDD)
VDD_EXT: C404.1 R403.2 R404.2 U400.3(PVDD)
AUD_N: C406.1 R410.1
AUD_P: C407.1 R411.1
CODEC_I2S_BCLK: C408.2 R405.2 U400.6(SCLK/DMIC_SCL) ; off-sheet CODEC_I2S_BCLK
CODEC_I2S_DIN: C405.2 R406.1 ; off-sheet CODEC_I2S_DIN
CODEC_I2S_DOUT: C402.2 U400.9(DSDIN) ; off-sheet CODEC_I2S_DOUT
CODEC_I2S_LRCK: C403.2 U400.8(LRCK) ; off-sheet CODEC_I2S_LRCK
CODEC_I2S_MCLK: C409.2 R405.1 U400.2(MCLK) ; off-sheet CODEC_I2S_MCLK
FLASH_CLK: U402.6(SCLK) ; off-sheet FLASH_CLK
FLASH_CS: U402.1(CS) ; off-sheet FLASH_CS
FLASH_MISO: R417.1 ; off-sheet FLASH_MISO
FLASH_MOSI: U402.5(SI/SIO0) ; off-sheet FLASH_MOSI
I2C0_SCL: R404.1 U400.1(CCLK) ; off-sheet I2C0_SCL
I2C0_SDA: R403.1 U400.19(CDATA) ; off-sheet I2C0_SDA
MIC_N: C415.2 CON401.2 R413.2 R416.2
MIC_P: C414.2 CON401.1 R412.2 R415.1
PA_SD: R400.1 ; off-sheet PA_SD
NetC406_2: C406.2 R407.1
NetC407_2: C407.2 R408.1
NetC410_2: C410.2 U401.2(BYPASS)
NetC414_1: C414.1 U400.18(MIC1P/DMIC_SDA)
NetC415_1: C415.1 U400.17(MIC1N)
NetC416_2: C416.2 U400.16(VMID)
NetC417_2: C417.2 U400.15(ADCVREF)
NetC418_2: C418.2 U400.14(DACVREF)
NetC420_1: C420.1 R414.1 R415.2
NetC421_2: C421.2 D400.K R412.1 U403.4(OUT)
NetCON400_1: CON400.1 U401.5(OUTN)
NetCON400_2: CON400.2 U401.8(OUTP)
NetR400_2: R400.2 R401.1 R402.2 U401.1(SD)
NetR406_2: R406.2 U400.7(ASDOUT)
NetR407_2: R407.2 U401.4(INN)
NetR408_2: R408.2 U401.3(INP)
NetR409_1: R409.1 U400.20(CE)
NetR410_2: R410.2 U400.13(OUTN)
NetR411_2: R411.2 U400.12(OUTP)
NetR417_2: R417.2 U402.2(SO/SIO1)
NetR418_2: R418.2 U402.3(SIO2)
NetR419_1: R419.1 U402.7(SIO3)

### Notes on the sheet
- Codec
- (near R409) I2C Address
- (near R409) 0x18
- 1.25mm/2Pin/Vertical
- PA
- FLASH
- Fc=1/(2*pi*Rin*Cin)=4.85 Hz
- Av=300/Rin=4.3 v/v
- (near U402) 3.3V(SH) 150mil(SSH)
- 1.5mm/2Pin/Right-Angle
- PCB Name:
- PCB Model:
- Designer：
- Proj. Code:
- Design Date:
- PCB Ver.:
- Paper Size:
- 4
- Reviewed by:
- Review Date:
- Page __ of __

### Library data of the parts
C400 C414 C415 C419 = 1405001497: 2.2uF/6.3V/20%/X5R; 产品型号: CL05A225MQ5NNNC; 品名: 陶瓷电容; 原厂品牌: SAMSUNG电容; 封装: 0402; 物料状态: 优选
C401 C404 C413 C416-C418 C420 = 1405002136: as C100 on sheet 01_NT26FxDx
C402 C403 C405 C408 C409 = 1405000291: 33pF/50V/5%/C0G; 产品型号: CC0402JRNPO9BN330; 品名: 陶瓷电容; 原厂品牌: YAGEO; 封装: 0402; 物料状态: 优选
C406 C407 = 1405005412: 22nF/10V/10%/X5R; 产品型号: V223K0201X5R100NAT; 品名: 陶瓷电容; 原厂品牌: 微容VIIYONG; 封装: 0201; 物料状态: 优选
C410 = 1405005056: 1uF/10V/20%/X5R; 产品型号: V105M0201X5R100NXT; 品名: 陶瓷电容; 原厂品牌: 微容VIIYONG; 封装: 0201; 物料状态: 优选
C411 = 1405001308: as C103 on sheet 01_NT26FxDx
C412 C422 C423 = 1405001272: 0.1uF/10V/10%/X5R; 产品型号: V104K0201X5R100NAT; 品名: 陶瓷电容; 原厂品牌: 微容VIIYONG; 封装: 0201; 物料状态: 优选
C421 = 1405001343: 15pF/50V/5%/C0G; 产品型号: V150J0201C0G500NAT; 品名: 陶瓷电容; 原厂品牌: 微容VIIYONG; 封装: 0201; 物料状态: 优选
CON400 = 1416003013: 1.25mm/2PIN; 产品型号: CNT-W125-1*2-TSM; 品名: 线对板连接器; 原厂品牌: 肯耐特; 封装: SMD; 物料状态: 优选
CON401 = 1416002711: 1.25mm/2PIN; 品名: 线对板连接器; 原厂品牌: 乐清华宝; 封装: SMD; 物料状态: 优选
D400 = 1409004149: as D100 on sheet 01_NT26FxDx
JP400 = RES: 产品型号: JP
R400-R402 R407 R408 = 1408001835: as R125 on sheet 01_NT26FxDx
R403-R406 R409 R414-R419 = 1408001443: as R104 on sheet 01_NT26FxDx
R410-R413 = 1408001445: 1KΩ/5%; 产品型号: RC0201JR-071KL; 品名: 厚膜贴片电阻; 原厂品牌: YAGEO; 封装: 0201; 物料状态: 优选
U400 = ES8311: QFN20-3*3mm
U402 = P25Q64SLA-SUH-IR
U403 = SI-MIC: 1406000322

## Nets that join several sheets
3V3: 01_NT26FxDx (C118.2 TP113.1 U105.5), 02_Interfaces (C200.2 C201.1 CON200.20 P200.3), 04_CODEC_PA (14 pins)
CAM_VDD: 01_NT26FxDx (C117.2 TP112.1 U104.5), 02_Interfaces (C213.1 CON201.4 D200.K)
GND: 01_NT26FxDx (73 pins), 02_Interfaces (24 pins), 03_LED_KEY (39 pins), 04_CODEC_PA (22 pins)
VBAT: 01_NT26FxDx (16 pins), 03_LED_KEY (Q300.S R305.1), 04_CODEC_PA (C411.1 C412.2 U401.6)
VBUS: 01_NT26FxDx (14 pins), 03_LED_KEY (R301.2)
VDD_EXT: 01_NT26FxDx (C109.2 R100.1 U102.24), 02_Interfaces (6 pins), 03_LED_KEY (K300.3 K300.4 TP306.1), 04_CODEC_PA (C404.1 R403.2 R404.2 U400.3)
CAM_MCLK: 01_NT26FxDx (R119.1), 02_Interfaces (C208.2 CON201.13)
CAM_PWDN: 01_NT26FxDx (U102.81), 02_Interfaces (CON201.8)
CAM_SPI_CLK: 01_NT26FxDx (U102.80), 02_Interfaces (C209.2 R202.1)
CAM_SPI_D0: 01_NT26FxDx (U102.55), 02_Interfaces (C210.2 R203.1)
CAM_SPI_D1: 01_NT26FxDx (U102.56), 02_Interfaces (C211.2 R204.1)
CHG_LED: 01_NT26FxDx (R102.2 U103.7), 03_LED_KEY (LED301.K)
CODEC_I2S_BCLK: 01_NT26FxDx (R106.2), 04_CODEC_PA (C408.2 R405.2 U400.6)
CODEC_I2S_DIN: 01_NT26FxDx (U102.32), 04_CODEC_PA (C405.2 R406.1)
CODEC_I2S_DOUT: 01_NT26FxDx (R104.2), 04_CODEC_PA (C402.2 U400.9)
CODEC_I2S_LRCK: 01_NT26FxDx (R105.2), 04_CODEC_PA (C403.2 U400.8)
CODEC_I2S_MCLK: 01_NT26FxDx (R107.2), 04_CODEC_PA (C409.2 R405.1 U400.2)
FLASH_CLK: 01_NT26FxDx (R114.2), 04_CODEC_PA (U402.6)
FLASH_CS: 01_NT26FxDx (U102.64), 04_CODEC_PA (U402.1)
FLASH_MISO: 01_NT26FxDx (U102.62), 04_CODEC_PA (R417.1)
FLASH_MOSI: 01_NT26FxDx (R123.2), 04_CODEC_PA (U402.5)
I2C0_SCL: 01_NT26FxDx (TP102.1 U102.39), 02_Interfaces (CON201.5 R201.1), 04_CODEC_PA (R404.1 U400.1)
I2C0_SDA: 01_NT26FxDx (TP103.1 U102.38), 02_Interfaces (CON201.3 R200.1), 04_CODEC_PA (R403.1 U400.19)
I2C1_SCL: 01_NT26FxDx (R120.1 U102.57), 02_Interfaces (CON200.18 P200.2)
I2C1_SDA: 01_NT26FxDx (U102.66), 02_Interfaces (CON200.17 P200.1)
KEY_BOOT: 01_NT26FxDx (U102.82), 03_LED_KEY (5 pins)
KEY_USER0: 01_NT26FxDx (U102.5), 03_LED_KEY (C303.2 D303.K K303.3 TP303.1)
KEY_USER1: 01_NT26FxDx (U102.19), 03_LED_KEY (C304.2 D304.K K304.3 TP304.1)
KEY_USER2: 01_NT26FxDx (U102.87), 03_LED_KEY (C305.2 D305.K K305.3 TP305.1)
LCD_CLK: 01_NT26FxDx (R117.1), 02_Interfaces (C203.2 CON200.6)
LCD_CS1: 01_NT26FxDx (U102.52), 02_Interfaces (CON200.12)
LCD_CS2: 01_NT26FxDx (R120.2), 02_Interfaces (CON200.11)
LCD_D0: 01_NT26FxDx (R115.1), 02_Interfaces (C207.2 CON200.1)
LCD_D1: 01_NT26FxDx (R116.1), 02_Interfaces (C206.2 CON200.2)
LCD_D2: 01_NT26FxDx (R134.2), 02_Interfaces (C205.2 CON200.3)
LCD_D3: 01_NT26FxDx (R133.2), 02_Interfaces (C204.2 CON200.4)
LCD_LED: 01_NT26FxDx (U102.103), 02_Interfaces (CON200.10)
LCD_RST: 01_NT26FxDx (U102.78), 02_Interfaces (CON200.13)
LCD_TE: 01_NT26FxDx (U102.58), 02_Interfaces (CON200.8)
LDO33_EN: 01_NT26FxDx (R128.1 U102.16), 03_LED_KEY (Q301.G R306.2)
PA_SD: 01_NT26FxDx (U102.29), 04_CODEC_PA (R400.1)
PWRKEY: 01_NT26FxDx (U102.7), 03_LED_KEY (C301.2 D301.K K301.3 TP301.1)
RESET: 01_NT26FxDx (U102.15), 03_LED_KEY (C302.2 D302.K K302.3 TP302.1)
RGB_LED: 01_NT26FxDx (U102.67), 03_LED_KEY (R300.2)
STDBY_LED: 01_NT26FxDx (U103.6), 03_LED_KEY (LED300.K)
TP_INT: 01_NT26FxDx (U102.6), 02_Interfaces (CON200.15)
TP_RST: 01_NT26FxDx (U102.28), 02_Interfaces (CON200.16)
